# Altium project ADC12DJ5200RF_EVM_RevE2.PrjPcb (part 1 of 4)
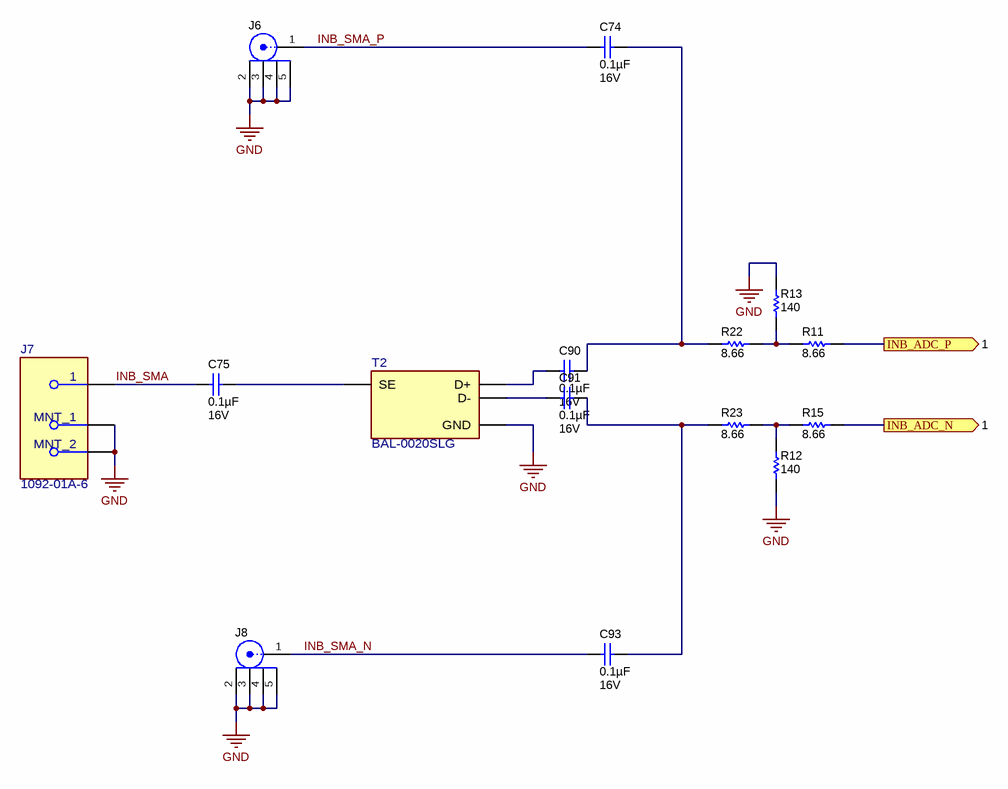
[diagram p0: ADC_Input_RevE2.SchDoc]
CopyrightYear: 2020; EVM_Orderable: N/A; PCB_Layout: DWG; PCB_Rev: E2; PRJ_Customer: Not For Public Release; PRJ_Engineer: DWG; PRJ_Number: N/A; PRJ_Title: ADC12DJ5200RF EVM; Rev: E2; TechSupport: http://www.ti.com/support; TID: N/A
15 sheets, 702 parts. Net scope: flat (ports and power ports of the same name join across sheets).
Board file: ADC12DJ5200RF_EVM_RevE2.PcbDoc
Sheets:
  ADC_Input_RevE2.SchDoc
  ADC_Power_RevE2.SchDoc
  ADC_RevE2.SchDoc
  Analog_Frontend_RevE2.SchDoc
  Clocks_RevE2.SchDoc
  Clocks2_RevE2.SchDoc
  Clocks3_RevE2.SchDoc
  FMC_RevE2.SchDoc
  GPIO_RevE2.SchDoc
  GPIO2_RevE2.SchDoc
  Misc_RevE2.SchDoc
  Power1_RevE2.SchDoc
  Power2_RevE2.SchDoc
  USB_RevE2.SchDoc
  Balun Test RevE2.SchDoc

## Sheet ADC_Input_RevE2.SchDoc: ADC EVM RF Input
size 431 x 279 mm; Date: Not shown in title block; ApprovedBy: Not shown in title block; CheckedBy: Not shown in title block; Author: Not shown in title block; CompanyName: Not shown in title block; DrawnBy: DWG; Engineer: Not shown in title block; Organization: Not shown in title block; Address1: Not shown in title block; Address2: Not shown in title block; Address3: Not shown in title block; Address4: Not shown in title block; DocumentNumber: 1; Revision: Use project parameter SCH_Rev; SheetNumber: 1; SheetTotal: 15; PageSetup: Record=PageOptions¦CenterHorizontal=True¦CenterVertical=True¦PrintScale=1.00¦XCorrection=1.00¦YCorrection=1.00¦PrintKind=0¦BorderSize=5000000¦LeftOffset=0¦BottomOffset=0¦Orientation=2¦PaperLength=1000¦PaperWidth=1000¦Scale=100¦PaperSource=15¦PrintQuality=600¦MediaType=1¦DitherType=10¦PaperKind=Letter¦PrintScaleMode=1

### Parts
C74  ValueDisplayed: 0.1µF  VDC_V: 16V  [0201_033]  (hidden comment: 0201BB104KW160)
C75  ValueDisplayed: 0.1µF  VDC_V: 16V  [0201_033]  (hidden comment: 0201BB104KW160)
C90  ValueDisplayed: 0.1µF  VDC_V: 16V  [0201_033]  (hidden comment: 0201BB104KW160)
C91  ValueDisplayed: 0.1µF  VDC_V: 16V  [0201_033]  (hidden comment: 0201BB104KW160)
C93  ValueDisplayed: 0.1µF  VDC_V: 16V  [0201_033]  (hidden comment: 0201BB104KW160)
J6  SASF546-P26-X1  [CONN_LTI_SASF546-P26-X1]  (value not drawn)
J7  1092-01A-6  [FP-1092-01A-6_RF_JACK_18MM94_12MM7-MFG]
J8  SASF546-P26-X1  [CONN_LTI_SASF546-P26-X1]  (value not drawn)
R11  ValueDisplayed: 8.66  [0201]  (hidden comment: RC0201FR-078R66L)
R12  ValueDisplayed: 140  [0201]  (hidden comment: RC0201FR-07140RL)
R13  ValueDisplayed: 140  [0201]  (hidden comment: RC0201FR-07140RL)
R15  ValueDisplayed: 8.66  [0201]  (hidden comment: RC0201FR-078R66L)
R22  ValueDisplayed: 8.66  [0201]  (hidden comment: RC0201FR-078R66L)
R23  ValueDisplayed: 8.66  [0201]  (hidden comment: RC0201FR-078R66L)
T2  BAL-0020SLG  [FP-BAL-0020SLG_SMT_BALUN_12MM70_5MM08-MFG]

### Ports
INB_ADC_N (out, see 1), INB_ADC_P (out, see 1)

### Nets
GND: J6.2 J6.3 J6.4 J6.5 J7.2(MNT_1) J7.3(MNT_2) J8.2 J8.3 J8.4 J8.5 R12.1 R13.2 T2.4(GND)
INB_ADC_N: R15.2 ; port INB_ADC_N
INB_ADC_P: R11.2 ; port INB_ADC_P
INB_SMA: C75.2 J7.1
INB_SMA_N: C93.2 J8.1
INB_SMA_P: C74.2 J6.1
NetC74_1: C74.1 C90.1 R22.1
NetC75_1: C75.1 T2.1(SE)
NetC90_2: C90.2 T2.3(D+)
NetC91_1: C91.1 C93.1 R23.1
NetC91_2: C91.2 T2.2(D-)
NetR11_1: R11.1 R13.1 R22.2
NetR12_2: R12.2 R15.1 R23.2

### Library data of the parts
C74 C75 C90 C91 C93 = CMP-0860981-1: CAP, CERM, 0.1 µF, 16 V,+/- 10%, X7R, 0201; Manufacturer: Passive Plus; Value: 0.1uF; Polarized: N; SizeY_mm: 0.3; TaMin_C: -55°C; U/M: EA; Cap_Case: 0201; AEC Category: Q200; SizeZ_mm: 0.33; SizeArea_mm2: 0.18; SizeX_mm: 0.6; Cap_F: 100nF; SizeAreaWB_mm2: 2.08; TaMax_C: 125°C
J6 J8 = CMP-0055826-1: Connector, SMA,Vertical, Thru hole w/SMT center pin; Manufacturer: Lighthorse Technologies; CT: TRUE; Green_REACh: Incomplete; CNHeader: FALSE; Green_Lifecycle: Not Set
J7 = CMP-0088081-2: End Launch 2.92mm (K) 40 GHz Jack (Female) Standard Block; Manufacturer: Southwest Microwave; ContactFinish: Gold; Shrouded: true
R11 R15 R22 R23 = CMP-0750119-1: RES, 8.66, 1%, 0.05 W, 0201; Manufacturer: Yageo; Value2: 0.05W; VDC_V: 50V; SizeZ_mm: 0.26; Value_Code: 8R66; AEC Category: Q200; TempCo: 350 ppm/C; SizeAreaWB_mm2: 2.08; Power_W: 50mW; AEC Qualified: N; EIA_Code: E96; SizeArea_mm2: 0.18; SizeX_mm: 0.6; SizeY_mm: 0.3; Value: 8.66
R12 R13 = CMP-0027355-2: RES, 140, 1%, 0.05 W, 0201; Manufacturer: Yageo America; Power_W: 50mW; TempCo: 200 ppm/C; Value_Code: 140R; U/M: EA; Value: 140; EIA_Code: E96; SizeX_mm: 0.6; SizeY_mm: 0.3; SizeZ_mm: 0.26; Value2: 0.05W; SizeArea_mm2: 0.18; AEC Qualified: N; VDC_V: 25V; AEC Category: Q200
T2 = CMP-0090705-1: 10 MHz to 20 GHz 1:2 Balun, Surface Mount; Manufacturer: Marki Microwave; Bandwidth: 19.99GHz; Filter Type: Band Pass; Frequency_Fixed: 0.01-20GHz; AEC Qualified: No; Insertion Loss: 7dB; SizeZ_mm: 2.79mm

## Sheet ADC_Power_RevE2.SchDoc: ADC EVM Power
size 431 x 279 mm; Date: Not shown in title block; ApprovedBy: Not shown in title block; CheckedBy: Not shown in title block; Author: Not shown in title block; CompanyName: Not shown in title block; DrawnBy: DWG; Engineer: Not shown in title block; Organization: Not shown in title block; Address1: Not shown in title block; Address2: Not shown in title block; Address3: Not shown in title block; Address4: Not shown in title block; DocumentNumber: 2; Revision: Use project parameter SCH_Rev; SheetNumber: 2; SheetTotal: 15; PageSetup: Record=PageOptions¦CenterHorizontal=True¦CenterVertical=True¦PrintScale=1.00¦XCorrection=1.00¦YCorrection=1.00¦PrintKind=0¦BorderSize=5000000¦LeftOffset=0¦BottomOffset=0¦Orientation=2¦PaperLength=1000¦PaperWidth=1000¦Scale=100¦PaperSource=15¦PrintQuality=600¦MediaType=1¦DitherType=10¦PaperKind=Letter¦PrintScaleMode=1
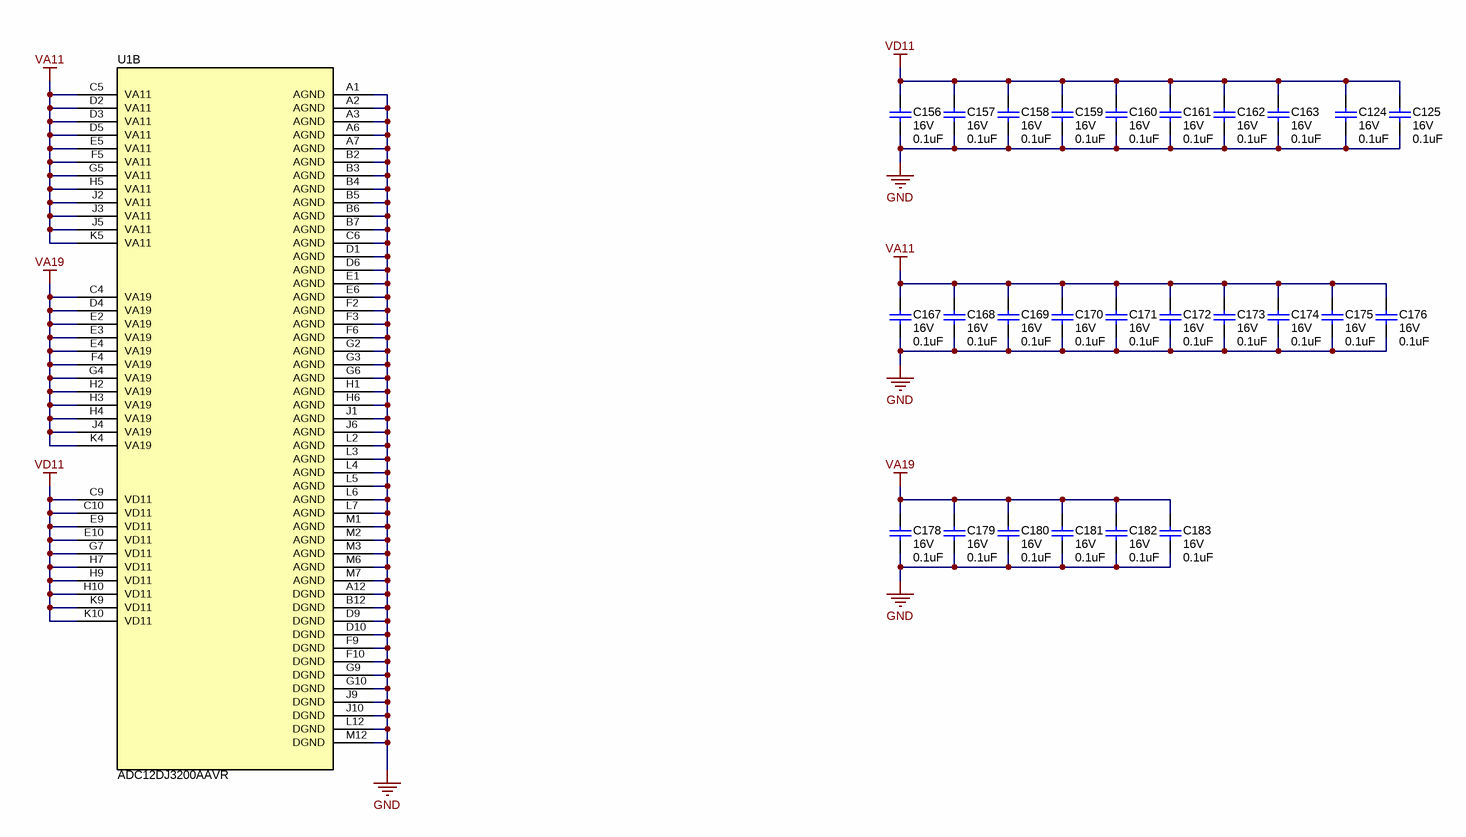
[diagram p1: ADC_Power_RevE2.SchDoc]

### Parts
C124  VDC_V: 16V  ValueDisplayed: 0.1uF  [0201L]  (hidden comment: GRM033Z71C104KE14D)
C125  VDC_V: 16V  ValueDisplayed: 0.1uF  [0201L]  (hidden comment: GRM033Z71C104KE14D)
C156  VDC_V: 16V  ValueDisplayed: 0.1uF  [0201L]  (hidden comment: GRM033Z71C104KE14D)
C157  VDC_V: 16V  ValueDisplayed: 0.1uF  [0201L]  (hidden comment: GRM033Z71C104KE14D)
C158  VDC_V: 16V  ValueDisplayed: 0.1uF  [0201L]  (hidden comment: GRM033Z71C104KE14D)
C159  VDC_V: 16V  ValueDisplayed: 0.1uF  [0201L]  (hidden comment: GRM033Z71C104KE14D)
C160  VDC_V: 16V  ValueDisplayed: 0.1uF  [0201L]  (hidden comment: GRM033Z71C104KE14D)
C161  VDC_V: 16V  ValueDisplayed: 0.1uF  [0201L]  (hidden comment: GRM033Z71C104KE14D)
C162  VDC_V: 16V  ValueDisplayed: 0.1uF  [0201L]  (hidden comment: GRM033Z71C104KE14D)
C163  VDC_V: 16V  ValueDisplayed: 0.1uF  [0201L]  (hidden comment: GRM033Z71C104KE14D)
C167  VDC_V: 16V  ValueDisplayed: 0.1uF  [0201L]  (hidden comment: GRM033Z71C104KE14D)
C168  VDC_V: 16V  ValueDisplayed: 0.1uF  [0201L]  (hidden comment: GRM033Z71C104KE14D)
C169  VDC_V: 16V  ValueDisplayed: 0.1uF  [0201L]  (hidden comment: GRM033Z71C104KE14D)
C170  VDC_V: 16V  ValueDisplayed: 0.1uF  [0201L]  (hidden comment: GRM033Z71C104KE14D)
C171  VDC_V: 16V  ValueDisplayed: 0.1uF  [0201L]  (hidden comment: GRM033Z71C104KE14D)
C172  VDC_V: 16V  ValueDisplayed: 0.1uF  [0201L]  (hidden comment: GRM033Z71C104KE14D)
C173  VDC_V: 16V  ValueDisplayed: 0.1uF  [0201L]  (hidden comment: GRM033Z71C104KE14D)
C174  VDC_V: 16V  ValueDisplayed: 0.1uF  [0201L]  (hidden comment: GRM033Z71C104KE14D)
C175  VDC_V: 16V  ValueDisplayed: 0.1uF  [0201L]  (hidden comment: GRM033Z71C104KE14D)
C176  VDC_V: 16V  ValueDisplayed: 0.1uF  [0201L]  (hidden comment: GRM033Z71C104KE14D)
C178  VDC_V: 16V  ValueDisplayed: 0.1uF  [0201L]  (hidden comment: GRM033Z71C104KE14D)
C179  VDC_V: 16V  ValueDisplayed: 0.1uF  [0201L]  (hidden comment: GRM033Z71C104KE14D)
C180  VDC_V: 16V  ValueDisplayed: 0.1uF  [0201L]  (hidden comment: GRM033Z71C104KE14D)
C181  VDC_V: 16V  ValueDisplayed: 0.1uF  [0201L]  (hidden comment: GRM033Z71C104KE14D)
C182  VDC_V: 16V  ValueDisplayed: 0.1uF  [0201L]  (hidden comment: GRM033Z71C104KE14D)
C183  VDC_V: 16V  ValueDisplayed: 0.1uF  [0201L]  (hidden comment: GRM033Z71C104KE14D)
U1  ADC12DJ3200AAVR  [AAV0144A]  (part B of 2)

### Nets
GND: C124.1 C125.1 C156.1 C157.1 C158.1 C159.1 C160.1 C161.1 C162.1 C163.1 C167.1 C168.1 C169.1 C170.1 C171.1 C172.1 C173.1 C174.1 C175.1 C176.1 C178.1 C179.1 C180.1 C181.1 C182.1 C183.1 U1.A1(AGND) U1.A2(AGND) U1.A3(AGND) U1.A6(AGND) U1.A7(AGND) U1.A12(DGND) U1.B2(AGND) U1.B3(AGND) U1.B4(AGND) U1.B5(AGND) U1.B6(AGND) U1.B7(AGND) U1.B12(DGND) U1.C6(AGND) U1.D1(AGND) U1.D6(AGND) U1.D9(DGND) U1.D10(DGND) U1.E1(AGND) U1.E6(AGND) U1.F2(AGND) U1.F3(AGND) U1.F6(AGND) U1.F9(DGND) U1.F10(DGND) U1.G2(AGND) U1.G3(AGND) U1.G6(AGND) U1.G9(DGND) U1.G10(DGND) U1.H1(AGND) U1.H6(AGND) U1.J1(AGND) U1.J6(AGND) U1.J9(DGND) U1.J10(DGND) U1.L2(AGND) U1.L3(AGND) U1.L4(AGND) U1.L5(AGND) U1.L6(AGND) U1.L7(AGND) U1.L12(DGND) U1.M1(AGND) U1.M2(AGND) U1.M3(AGND) U1.M6(AGND) U1.M7(AGND) U1.M12(DGND)
VA11: C167.2 C168.2 C169.2 C170.2 C171.2 C172.2 C173.2 C174.2 C175.2 C176.2 U1.C5(VA11) U1.D2(VA11) U1.D3(VA11) U1.D5(VA11) U1.E5(VA11) U1.F5(VA11) U1.G5(VA11) U1.H5(VA11) U1.J2(VA11) U1.J3(VA11) U1.J5(VA11) U1.K5(VA11)
VA19: C178.2 C179.2 C180.2 C181.2 C182.2 C183.2 U1.C4(VA19) U1.D4(VA19) U1.E2(VA19) U1.E3(VA19) U1.E4(VA19) U1.F4(VA19) U1.G4(VA19) U1.H2(VA19) U1.H3(VA19) U1.H4(VA19) U1.J4(VA19) U1.K4(VA19)
VD11: C124.2 C125.2 C156.2 C157.2 C158.2 C159.2 C160.2 C161.2 C162.2 C163.2 U1.C9(VD11) U1.C10(VD11) U1.E9(VD11) U1.E10(VD11) U1.G7(VD11) U1.H7(VD11) U1.H9(VD11) U1.H10(VD11) U1.K9(VD11) U1.K10(VD11)

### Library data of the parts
C124 C125 C156 C167 = CMP-0064970-1: CAP, CERM, 0.1 uF, 16 V,+/- 10%, X7R, 0201; Manufacturer: MuRata; TaMin_C: -55°C; Polarized: N; SizeAreaWB_mm2: 2.08; Value1: Unknown; U/M: EA; Value: 0.1uF; TaMax_C: 125°C; SizeZ_mm: 0.26; SizeX_mm: 0.6; SizeY_mm: 0.3; Cap_Case: 0201; SizeArea_mm2: 0.18; CompType: Capacitor; Cap_F: 100nF; AEC Category: Q200
C157-C163 C168-C176 C178-C183 = CMP-0064970-1: CAP, CERM, 0.1 uF, 16 V,+/- 10%, X7R, 0201; Manufacturer: MuRata; TaMin_C: -55°C; Polarized: N; SizeAreaWB_mm2: 2.08; Value1: Unknown; U/M: EA; Value: 0.1uF; TaMax_C: 125°C; SizeZ_mm: 0.26; SizeX_mm: 0.6; SizeY_mm: 0.3; Cap_Case: 0201; SizeArea_mm2: 0.18; Cap_F: 100nF; AEC Category: Q200
U1 = CMP-0065050-3: 6.4-GSPS Single Channel or 3.2-GSPS Dual Channel 12-bit Analog-to-Digital Converter (ADC) Family, AAV0144A (FCBGA-144); Alternate PartNumber: ADC12DJ3200AAVT; Manufacturer: Texas Instruments; SizeZ_mm: 1.94; SizeX_mm: 10.0; SizeArea_mm2: 100.0; CompType: IC; U/M: EA; SizeAreaWB_mm2: 144.0

## Sheet ADC_RevE2.SchDoc: ADC EVM IO
size 431 x 279 mm; Date: Not shown in title block; ApprovedBy: Not shown in title block; CheckedBy: Not shown in title block; Author: Not shown in title block; CompanyName: Not shown in title block; DrawnBy: DWG; Engineer: DWG; Organization: Not shown in title block; Address1: Not shown in title block; Address2: Not shown in title block; Address3: Not shown in title block; Address4: Not shown in title block; DocumentNumber: 3; Revision: Use project parameter SCH_Rev; SheetNumber: 3; SheetTotal: 15; PageSetup: Record=PageOptions¦CenterHorizontal=True¦CenterVertical=True¦PrintScale=1.00¦XCorrection=1.00¦YCorrection=1.00¦PrintKind=0¦BorderSize=5000000¦LeftOffset=0¦BottomOffset=0¦Orientation=2¦PaperLength=1000¦PaperWidth=1000¦Scale=100¦PaperSource=15¦PrintQuality=600¦MediaType=1¦DitherType=10¦PaperKind=Letter¦PrintScaleMode=1
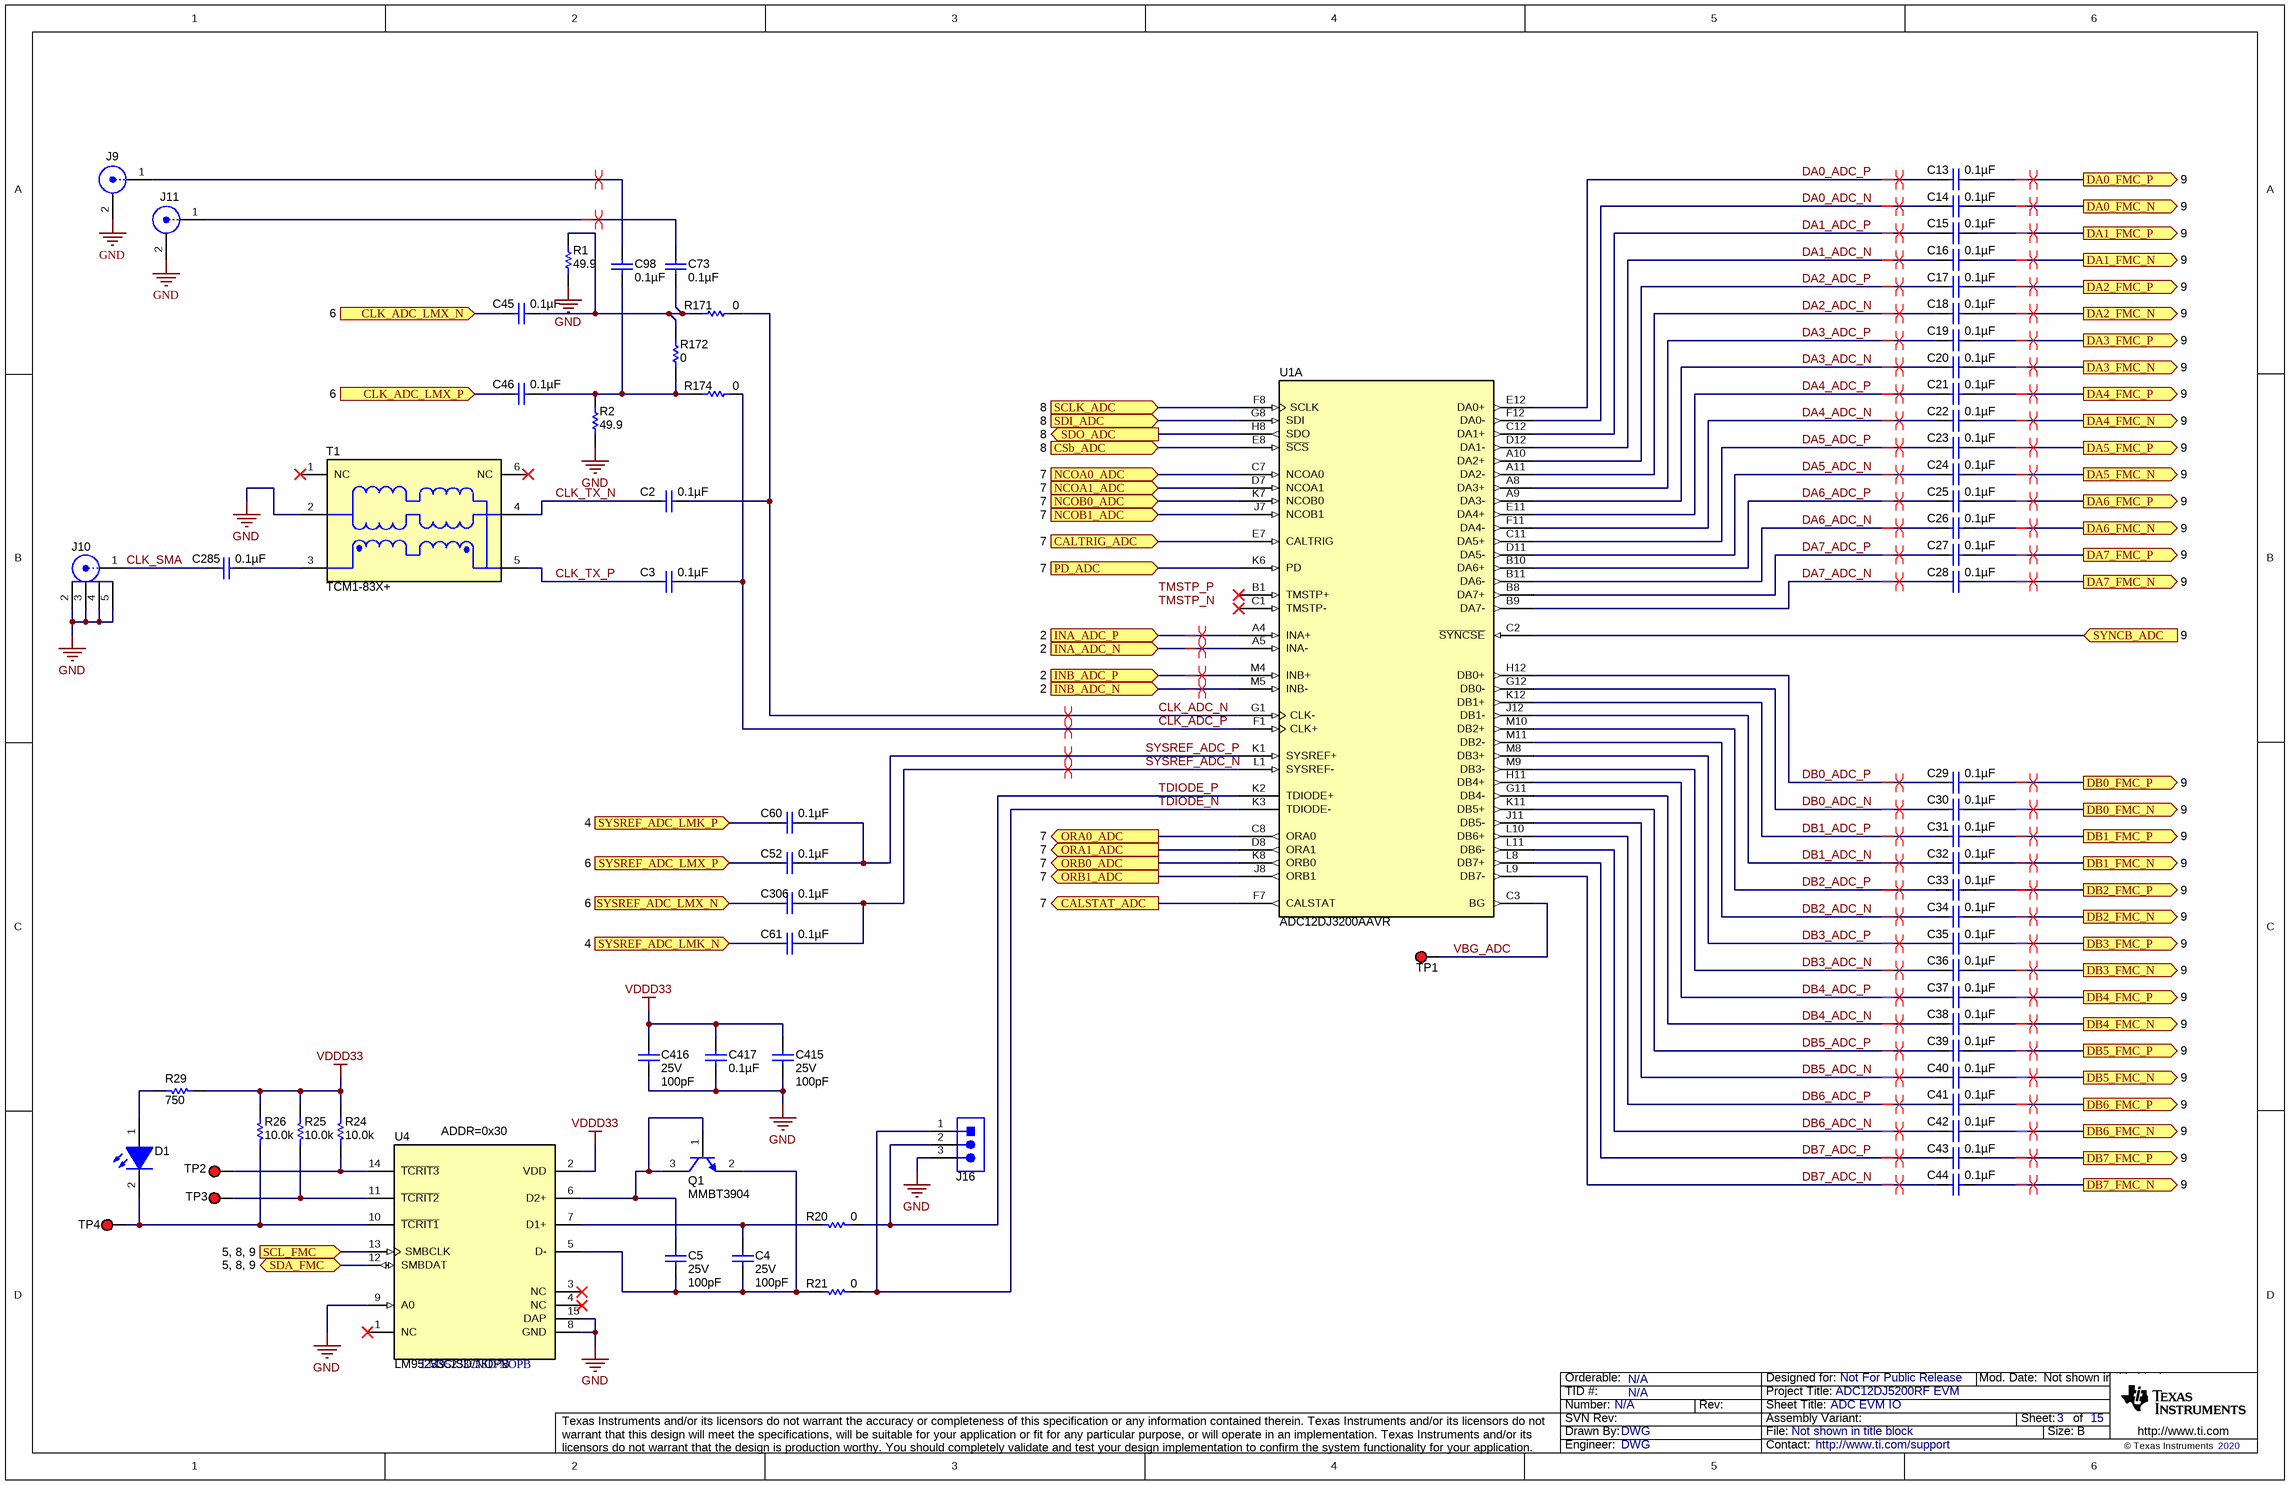
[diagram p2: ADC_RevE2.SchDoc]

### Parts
C2  ValueDisplayed: 0.1µF  [0201_033L]  (hidden comment: 0201BB104KW160)
C3  ValueDisplayed: 0.1µF  [0201_033L]  (hidden comment: 0201BB104KW160)
C4  VDC_V: 25V  ValueDisplayed: 100pF  [0201_033]  (hidden comment: C0603C0G1E101J030BA)
C5  VDC_V: 25V  ValueDisplayed: 100pF  [0201_033]  (hidden comment: C0603C0G1E101J030BA)
C13  ValueDisplayed: 0.1µF  [0201_033L]  (hidden comment: 0201BB104KW160)
C14  ValueDisplayed: 0.1µF  [0201_033L]  (hidden comment: 0201BB104KW160)
C15  ValueDisplayed: 0.1µF  [0201_033L]  (hidden comment: 0201BB104KW160)
C16  ValueDisplayed: 0.1µF  [0201_033L]  (hidden comment: 0201BB104KW160)
C17  ValueDisplayed: 0.1µF  [0201_033L]  (hidden comment: 0201BB104KW160)
C18  ValueDisplayed: 0.1µF  [0201_033L]  (hidden comment: 0201BB104KW160)
C19  ValueDisplayed: 0.1µF  [0201_033L]  (hidden comment: 0201BB104KW160)
C20  ValueDisplayed: 0.1µF  [0201_033L]  (hidden comment: 0201BB104KW160)
C21  ValueDisplayed: 0.1µF  [0201_033L]  (hidden comment: 0201BB104KW160)
C22  ValueDisplayed: 0.1µF  [0201_033L]  (hidden comment: 0201BB104KW160)
C23  ValueDisplayed: 0.1µF  [0201_033L]  (hidden comment: 0201BB104KW160)
C24  ValueDisplayed: 0.1µF  [0201_033L]  (hidden comment: 0201BB104KW160)
C25  ValueDisplayed: 0.1µF  [0201_033L]  (hidden comment: 0201BB104KW160)
C26  ValueDisplayed: 0.1µF  [0201_033L]  (hidden comment: 0201BB104KW160)
C27  ValueDisplayed: 0.1µF  [0201_033L]  (hidden comment: 0201BB104KW160)
C28  ValueDisplayed: 0.1µF  [0201_033L]  (hidden comment: 0201BB104KW160)
C29  ValueDisplayed: 0.1µF  [0201_033L]  (hidden comment: 0201BB104KW160)
C30  ValueDisplayed: 0.1µF  [0201_033L]  (hidden comment: 0201BB104KW160)
C31  ValueDisplayed: 0.1µF  [0201_033L]  (hidden comment: 0201BB104KW160)
C32  ValueDisplayed: 0.1µF  [0201_033L]  (hidden comment: 0201BB104KW160)
C33  ValueDisplayed: 0.1µF  [0201_033L]  (hidden comment: 0201BB104KW160)
C34  ValueDisplayed: 0.1µF  [0201_033L]  (hidden comment: 0201BB104KW160)
C35  ValueDisplayed: 0.1µF  [0201_033L]  (hidden comment: 0201BB104KW160)
C36  ValueDisplayed: 0.1µF  [0201_033L]  (hidden comment: 0201BB104KW160)
C37  ValueDisplayed: 0.1µF  [0201_033L]  (hidden comment: 0201BB104KW160)
C38  ValueDisplayed: 0.1µF  [0201_033L]  (hidden comment: 0201BB104KW160)
C39  ValueDisplayed: 0.1µF  [0201_033L]  (hidden comment: 0201BB104KW160)
C40  ValueDisplayed: 0.1µF  [0201_033L]  (hidden comment: 0201BB104KW160)
C41  ValueDisplayed: 0.1µF  [0201_033L]  (hidden comment: 0201BB104KW160)
C42  ValueDisplayed: 0.1µF  [0201_033L]  (hidden comment: 0201BB104KW160)
C43  ValueDisplayed: 0.1µF  [0201_033L]  (hidden comment: 0201BB104KW160)
C44  ValueDisplayed: 0.1µF  [0201_033L]  (hidden comment: 0201BB104KW160)
C45  ValueDisplayed: 0.1µF  [0201_033L]  (hidden comment: 0201BB104KW160)
C46  ValueDisplayed: 0.1µF  [0201_033L]  (hidden comment: 0201BB104KW160)
C52  ValueDisplayed: 0.1µF  [0201_033L]  (hidden comment: 0201BB104KW160)
C60  ValueDisplayed: 0.1µF  [0201_033L]  (hidden comment: 0201BB104KW160)
C61  ValueDisplayed: 0.1µF  [0201_033L]  (hidden comment: 0201BB104KW160)
C73  ValueDisplayed: 0.1µF  [0201_033L]  (hidden comment: 0201BB104KW160)
C98  ValueDisplayed: 0.1µF  [0201_033L]  (hidden comment: 0201BB104KW160)
C285  ValueDisplayed: 0.1µF  [0201_033L]  (hidden comment: 0201BB104KW160)
C306  ValueDisplayed: 0.1µF  [0201_033L]  (hidden comment: 0201BB104KW160)
C415  VDC_V: 25V  ValueDisplayed: 100pF  [0201_033]  (hidden comment: C0603C0G1E101J030BA)
C416  VDC_V: 25V  ValueDisplayed: 100pF  [0201_033]  (hidden comment: C0603C0G1E101J030BA)
C417  ValueDisplayed: 0.1µF  [0201_033L]  (hidden comment: 0201BB104KW160)
D1  LTST-C190KRKT  [LED_LTST-C190_Red]  (value not drawn)
J9  0853050232  [Molex_0853050232]  (value not drawn)
J10  SASF546-P26-X1  [CONN_LTI_SASF546-P26-X1]  (value not drawn)
J11  0853050232  [Molex_0853050232]  (value not drawn)
J16  61300311121  [WURTH_61300311121]  (value not drawn)
Q1  MMBT3904  [SOT-23]
R1  ValueDisplayed: 49.9  [0201L]  (hidden comment: ERJ-1GEF49R9C)
R2  ValueDisplayed: 49.9  [0201L]  (hidden comment: ERJ-1GEF49R9C)
R20  ValueDisplayed: 0  [0201]  (hidden comment: CRCW02010000Z0ED)
R21  ValueDisplayed: 0  [0201]  (hidden comment: CRCW02010000Z0ED)
R24  ValueDisplayed: 10.0k  [0201]  (hidden comment: RC0201FR-7D10KL)
R25  ValueDisplayed: 10.0k  [0201]  (hidden comment: RC0201FR-7D10KL)
R26  ValueDisplayed: 10.0k  [0201]  (hidden comment: RC0201FR-7D10KL)
R29  ValueDisplayed: 750  [0201]  (hidden comment: RC0201FR-07750RL)
R171  ValueDisplayed: 0  [0201L]  (hidden comment: CRCW02010000Z0ED)
R172  ValueDisplayed: 0  [0201L]  (hidden comment: CRCW02010000Z0ED)
R174  ValueDisplayed: 0  [0201L]  (hidden comment: CRCW02010000Z0ED)
T1  TCM1-83X+  [MNC_TCM1-83X+]
TP1  5000  [Keystone5000]  (value not drawn)
TP2  5000  [Keystone5000]  (value not drawn)
TP3  5000  [Keystone5000]  (value not drawn)
TP4  5000  [Keystone5000]  (value not drawn)
U1  ADC12DJ3200AAVR  [AAV0144A]  (part A of 2)
U4  LM95233CISD/NOPB  [NHL0014B]

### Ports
CALSTAT_ADC (out, see 7), CALTRIG_ADC (in, see 7), CLK_ADC_LMX_N (in, see 6), CLK_ADC_LMX_P (in, see 6), CSb_ADC (in, see 8), DA0_FMC_N (out, see 9), DA0_FMC_P (out, see 9), DA1_FMC_N (out, see 9), DA1_FMC_P (out, see 9), DA2_FMC_N (out, see 9), DA2_FMC_P (out, see 9), DA3_FMC_N (out, see 9), DA3_FMC_P (out, see 9), DA4_FMC_N (out, see 9), DA4_FMC_P (out, see 9), DA5_FMC_N (out, see 9), DA5_FMC_P (out, see 9), DA6_FMC_N (out, see 9), DA6_FMC_P (out, see 9), DA7_FMC_N (out, see 9), DA7_FMC_P (out, see 9), DB0_FMC_N (out, see 9), DB0_FMC_P (out, see 9), DB1_FMC_N (out, see 9), DB1_FMC_P (out, see 9), DB2_FMC_N (out, see 9), DB2_FMC_P (out, see 9), DB3_FMC_N (out, see 9), DB3_FMC_P (out, see 9), DB4_FMC_N (out, see 9), DB4_FMC_P (out, see 9), DB5_FMC_N (out, see 9), DB5_FMC_P (out, see 9), DB6_FMC_N (out, see 9), DB6_FMC_P (out, see 9), DB7_FMC_N (out, see 9), DB7_FMC_P (out, see 9), INA_ADC_N (in, see 2), INA_ADC_P (in, see 2), INB_ADC_N (in, see 2), INB_ADC_P (in, see 2), NCOA0_ADC (in, see 7), NCOA1_ADC (in, see 7), NCOB0_ADC (in, see 7), NCOB1_ADC (in, see 7), ORA0_ADC (out, see 7), ORA1_ADC (out, see 7), ORB0_ADC (out, see 7), ORB1_ADC (out, see 7), PD_ADC (in, see 7), SCL_FMC (in, see 5, 8, 9), SCLK_ADC (in, see 8), SDA_FMC (bidir, see 5, 8, 9), SDI_ADC (in, see 8), SDO_ADC (out, see 8), SYNCB_ADC (in, see 9), SYSREF_ADC_LMK_N (in, see 4), SYSREF_ADC_LMK_P (in, see 4), SYSREF_ADC_LMX_N (in, see 6), SYSREF_ADC_LMX_P (in, see 6)

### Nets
GND: C415.2 C416.2 C417.2 J9.2 J10.2 J10.3 J10.4 J10.5 J11.2 J16.3 R1.1 R2.1 T1.2 U4.8(GND) U4.9(A0) U4.15(DAP)
VDDD33: C415.1 C416.1 C417.1 R24.2 R25.2 R26.2 R29.1 U4.2(VDD)
CALSTAT_ADC: U1.F7(CALSTAT) ; port CALSTAT_ADC
CALTRIG_ADC: U1.E7(CALTRIG) ; port CALTRIG_ADC
CLK_ADC_LMX_N: C45.2 ; port CLK_ADC_LMX_N
CLK_ADC_LMX_P: C46.2 ; port CLK_ADC_LMX_P
CLK_ADC_N: C2.1 R171.2 U1.G1(CLK-)
CLK_ADC_P: C3.1 R174.2 U1.F1(CLK+)
CLK_SMA: C285.2 J10.1
CLK_TX_N: C2.2 T1.4
CLK_TX_P: C3.2 T1.5
CSb_ADC: U1.E8(~{SCS}) ; port CSb_ADC
DA0_ADC_N: C14.2 U1.F12(DA0-)
DA0_ADC_P: C13.2 U1.E12(DA0+)
DA0_FMC_N: C14.1 ; port DA0_FMC_N
DA0_FMC_P: C13.1 ; port DA0_FMC_P
DA1_ADC_N: C16.2 U1.D12(DA1-)
DA1_ADC_P: C15.2 U1.C12(DA1+)
DA1_FMC_N: C16.1 ; port DA1_FMC_N
DA1_FMC_P: C15.1 ; port DA1_FMC_P
DA2_ADC_N: C18.2 U1.A11(DA2-)
DA2_ADC_P: C17.2 U1.A10(DA2+)
DA2_FMC_N: C18.1 ; port DA2_FMC_N
DA2_FMC_P: C17.1 ; port DA2_FMC_P
DA3_ADC_N: C20.2 U1.A9(DA3-)
DA3_ADC_P: C19.2 U1.A8(DA3+)
DA3_FMC_N: C20.1 ; port DA3_FMC_N
DA3_FMC_P: C19.1 ; port DA3_FMC_P
DA4_ADC_N: C22.2 U1.F11(DA4-)
DA4_ADC_P: C21.2 U1.E11(DA4+)
DA4_FMC_N: C22.1 ; port DA4_FMC_N
DA4_FMC_P: C21.1 ; port DA4_FMC_P
DA5_ADC_N: C24.2 U1.D11(DA5-)
DA5_ADC_P: C23.2 U1.C11(DA5+)
DA5_FMC_N: C24.1 ; port DA5_FMC_N
DA5_FMC_P: C23.1 ; port DA5_FMC_P
DA6_ADC_N: C26.2 U1.B11(DA6-)
DA6_ADC_P: C25.2 U1.B10(DA6+)
DA6_FMC_N: C26.1 ; port DA6_FMC_N
DA6_FMC_P: C25.1 ; port DA6_FMC_P
DA7_ADC_N: C28.2 U1.B9(DA7-)
DA7_ADC_P: C27.2 U1.B8(DA7+)
DA7_FMC_N: C28.1 ; port DA7_FMC_N
DA7_FMC_P: C27.1 ; port DA7_FMC_P
DB0_ADC_N: C30.2 U1.G12(DB0-)
DB0_ADC_P: C29.2 U1.H12(DB0+)
DB0_FMC_N: C30.1 ; port DB0_FMC_N
DB0_FMC_P: C29.1 ; port DB0_FMC_P
DB1_ADC_N: C32.2 U1.J12(DB1-)
DB1_ADC_P: C31.2 U1.K12(DB1+)
DB1_FMC_N: C32.1 ; port DB1_FMC_N
DB1_FMC_P: C31.1 ; port DB1_FMC_P
DB2_ADC_N: C34.2 U1.M11(DB2-)
DB2_ADC_P: C33.2 U1.M10(DB2+)
DB2_FMC_N: C34.1 ; port DB2_FMC_N
DB2_FMC_P: C33.1 ; port DB2_FMC_P
DB3_ADC_N: C36.2 U1.M9(DB3-)
DB3_ADC_P: C35.2 U1.M8(DB3+)
DB3_FMC_N: C36.1 ; port DB3_FMC_N
DB3_FMC_P: C35.1 ; port DB3_FMC_P
DB4_ADC_N: C38.2 U1.G11(DB4-)
DB4_ADC_P: C37.2 U1.H11(DB4+)
DB4_FMC_N: C38.1 ; port DB4_FMC_N
DB4_FMC_P: C37.1 ; port DB4_FMC_P
DB5_ADC_N: C40.2 U1.J11(DB5-)
DB5_ADC_P: C39.2 U1.K11(DB5+)
DB5_FMC_N: C40.1 ; port DB5_FMC_N
DB5_FMC_P: C39.1 ; port DB5_FMC_P
DB6_ADC_N: C42.2 U1.L11(DB6-)
DB6_ADC_P: C41.2 U1.L10(DB6+)
DB6_FMC_N: C42.1 ; port DB6_FMC_N
DB6_FMC_P: C41.1 ; port DB6_FMC_P
DB7_ADC_N: C44.2 U1.L9(DB7-)
DB7_ADC_P: C43.2 U1.L8(DB7+)
DB7_FMC_N: C44.1 ; port DB7_FMC_N
DB7_FMC_P: C43.1 ; port DB7_FMC_P
INA_ADC_N: U1.A5(INA-) ; port INA_ADC_N
INA_ADC_P: U1.A4(INA+) ; port INA_ADC_P
INB_ADC_N: U1.M5(INB-) ; port INB_ADC_N
INB_ADC_P: U1.M4(INB+) ; port INB_ADC_P
NCOA0_ADC: U1.C7(NCOA0) ; port NCOA0_ADC
NCOA1_ADC: U1.D7(NCOA1) ; port NCOA1_ADC
NCOB0_ADC: U1.K7(NCOB0) ; port NCOB0_ADC
NCOB1_ADC: U1.J7(NCOB1) ; port NCOB1_ADC
ORA0_ADC: U1.C8(ORA0) ; port ORA0_ADC
ORA1_ADC: U1.D8(ORA1) ; port ORA1_ADC
ORB0_ADC: U1.K8(ORB0) ; port ORB0_ADC
ORB1_ADC: U1.J8(ORB1) ; port ORB1_ADC
PD_ADC: U1.K6(PD) ; port PD_ADC
SCL_FMC: U4.13(SMBCLK) ; port SCL_FMC
SCLK_ADC: U1.F8(SCLK) ; port SCLK_ADC
SDA_FMC: U4.12(SMBDAT) ; port SDA_FMC
SDI_ADC: U1.G8(SDI) ; port SDI_ADC
SDO_ADC: U1.H8(SDO) ; port SDO_ADC
SYNCB_ADC: U1.C2(~{SYNCSE}) ; port SYNCB_ADC
SYSREF_ADC_LMK_N: C61.2 ; port SYSREF_ADC_LMK_N
SYSREF_ADC_LMK_P: C60.2 ; port SYSREF_ADC_LMK_P
SYSREF_ADC_LMX_N: C306.2 ; port SYSREF_ADC_LMX_N
SYSREF_ADC_LMX_P: C52.2 ; port SYSREF_ADC_LMX_P
SYSREF_ADC_N: C61.1 C306.1 U1.L1(SYSREF-)
SYSREF_ADC_P: C52.1 C60.1 U1.K1(SYSREF+)
TDIODE_N: J16.1 R21.1 U1.K3(TDIODE-)
TDIODE_P: J16.2 R20.1 U1.K2(TDIODE+)
VBG_ADC: TP1.1 U1.C3(BG)
NetC4_1: C4.1 R20.2 U4.7(D1+)
NetC4_2: C4.2 C5.2 Q1.2(E) R21.2 U4.5(D-)
NetC5_1: C5.1 Q1.1(B) Q1.3(C) U4.6(D2+)
NetC45_1: C45.1 C73.2 R1.2 R171.1 R172.2
NetC46_1: C46.1 C98.2 R2.2 R172.1 R174.1
NetC73_1: C73.1 J11.1
NetC98_1: C98.1 J9.1
NetC285_1: C285.1 T1.3
NetD1_1: D1.1(A) R29.2
NetD1_2: D1.2(K) R26.1 TP4.1 U4.10(~{TCRIT1})
NetR24_1: R24.1 TP2.1 U4.14(~{TCRIT3})
NetR25_1: R25.1 TP3.1 U4.11(~{TCRIT2})

Not connected (* = marked no-connect by the designer): T1 1(NC)* 6(NC)*; U1 B1(TMSTP+)* C1(TMSTP-)*; U4 1(NC)* 3(NC)* 4(NC)*

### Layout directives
differential pair: CLK_ADC_N, CLK_ADC_P, DA0_ADC_N, DA0_ADC_P, DA0_FMC_N, DA0_FMC_P, DA1_ADC_N, DA1_ADC_P, DA1_FMC_N, DA1_FMC_P, DA2_ADC_N, DA2_ADC_P, DA2_FMC_N, DA2_FMC_P, DA3_ADC_N, DA3_ADC_P, DA3_FMC_N, DA3_FMC_P, DA4_ADC_N, DA4_ADC_P, DA4_FMC_N, DA4_FMC_P, DA5_ADC_N, DA5_ADC_P, DA5_FMC_N, DA5_FMC_P, DA6_ADC_N, DA6_ADC_P, DA6_FMC_N, DA6_FMC_P, DA7_ADC_N, DA7_ADC_P, DA7_FMC_N, DA7_FMC_P, DB0_ADC_N, DB0_ADC_P, DB0_FMC_N, DB0_FMC_P, DB1_ADC_N, DB1_ADC_P, DB1_FMC_N, DB1_FMC_P, DB2_ADC_N, DB2_ADC_P, DB2_FMC_N, DB2_FMC_P, DB3_ADC_N, DB3_ADC_P, DB3_FMC_N, DB3_FMC_P, DB4_ADC_N, DB4_ADC_P, DB4_FMC_N, DB4_FMC_P, DB5_ADC_N, DB5_ADC_P, DB5_FMC_N, DB5_FMC_P, DB6_ADC_N, DB6_ADC_P, DB6_FMC_N, DB6_FMC_P, DB7_ADC_N, DB7_ADC_P, DB7_FMC_N, DB7_FMC_P, INA_ADC_N, INA_ADC_P, INB_ADC_N, INB_ADC_P, NetC73_1, NetC98_1, SYSREF_ADC_N, SYSREF_ADC_P

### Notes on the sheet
- (near U4) ADDR=0x30
- Labels drawn without touching a wire or pin: TMSTP_N, TMSTP_P

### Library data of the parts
C2 C3 C13-C46 C52 C60 C61 C73 C98 C285 C306 C417 = CMP-0860981-1: CAP, CERM, 0.1 µF, 16 V,+/- 10%, X7R, 0201; Manufacturer: Passive Plus; Cap_F: 100nF; SizeAreaWB_mm2: 2.08; SizeArea_mm2: 0.18; AEC Qualified: N; AEC Category: Q200; Value: 0.1uF; TaMax_C: 125°C; SizeZ_mm: 0.33; TaMin_C: -55°C; VDC_V: 16V; SizeY_mm: 0.3; U/M: EA; SizeX_mm: 0.6; Cap_Case: 0201
C4 C5 C415 C416 = CMP-0009632-3: CAP, CERM, 100 pF, 25 V, +/- 5%, C0G/NP0, 0201; Manufacturer: TDK; TaMin_C: -55°C; Polarized: N; SizeAreaWB_mm2: 2.08; Value1: Unknown; U/M: EA; Value: 100pF; TaMax_C: 125°C; SizeZ_mm: 0.33; SizeX_mm: 0.6; SizeY_mm: 0.3; Cap_Case: 0201; SizeArea_mm2: 0.18; AEC Category: Q200
D1 = CMP-0078131-2: LED, Red, SMD; Manufacturer: Lite-On; Vr_V: 5V; Power_TotalModule: 62.5mW; Angle: 130; Ir_A: 10µA; Green_REACh: Incomplete; Io_A: 20mA; Vf_V: 2V; Green_Lifecycle: Not Set; Value1: .0625W; Type: AlInGaP
J9 J11 = CMP-0077224-1: Plug, 50 Ohm, Straight, SMT; Manufacturer: Molex; Cert_UL: Y; ContactFinish: Gold; CT: False; Gender: Male; Voltage_V: 335V
J10 = CMP-0055826-1: as J6 on sheet ADC_Input_RevE2
J16 = CMP-0054796-2: Header, 2.54 mm, 3x1, Gold, TH; Manufacturer: Wurth Elektronik; Green_Lifecycle: Active; Green_REACh: Passed; Cert_UL: Y; Gender: Male; Pitch_mm: 2.54; Row_Count: 1; Shrouded: N
Q1 = CMP-0000386-2: Transistor, NPN, 40 V, 0.2 A, SOT-23; Manufacturer: Fairchild Semiconductor; TaMax_C: 150°C; Value2: 300; Value1: 0.2 A; Vcesat1_V: 2dV; SizeX_mm: 2.5; SizeY_mm: 3; TaMin_C: -55°C; IcRated_A: 2dA; CompType: BJT; SizeZ_mm: 1.1; Value: 40 V; SizeArea_mm2: 7.5; NPN: 1; Vceo_V: 40V; PNP: 0; AEC Category: Q101; SizeAreaWB_mm2: 14; U/M: EA
R1 R2 = CMP-0027289-3: RES, 49.9, 1%, 0.05 W, AEC-Q200 Grade 1, 0201; Manufacturer: Panasonic; Power_W: 50mW; TempCo: 200 ppm/C; Value_Code: 49R9; Value: 49.9; EIA_Code: E96; SizeX_mm: 0.6; SizeY_mm: 0.3; SizeZ_mm: 0.26; Value2: 0.05W; SizeArea_mm2: 0.18; AEC Qualified: Y; VDC_V: 25V; AEC Category: Q200; AEC Grade: 1; SizeAreaWB_mm2: 2.08
R20 R21 = CMP-0027008-4: RES, 0, 5%, 0.05 W, 0201; Manufacturer: Vishay-Dale; Power_W: 50mW; TempCo: ppm/C; Value_Code: 0000; Value: 0; EIA_Code: E24; SizeX_mm: 0.6; SizeY_mm: 0.3; SizeZ_mm: 0.26; Value2: 0.05W; SizeArea_mm2: 0.18; AEC Qualified: N; AEC Category: Q200
R24-R26 = CMP-0027945-1: RES, 10.0 k, 1%, 0.05 W, 0201; Manufacturer: Yageo America; Power_W: 50mW; TempCo: 200 ppm/C; Value_Code: 10k0; U/M: EA; Value: 10.0k; EIA_Code: E96; Res_ohm: 10k; SizeX_mm: 0.6; SizeY_mm: 0.3; SizeZ_mm: 0.26; Value2: 0.05W; SizeArea_mm2: 0.18; AEC Qualified: N; VDC_V: 25V; AEC Category: Q200
R29 = CMP-0027865-1: RES, 750, 1%, 0.05 W, 0201; Manufacturer: Yageo America; Power_W: 50mW; TempCo: 200 ppm/C; Value_Code: 750R; U/M: EA; Value: 750; EIA_Code: E96; SizeX_mm: 0.6; SizeY_mm: 0.3; SizeZ_mm: 0.26; Value2: 0.05W; SizeArea_mm2: 0.18; AEC Qualified: N; VDC_V: 25V; AEC Category: Q200
R171 R172 R174 = CMP-0027008-4: RES, 0, 5%, 0.05 W, 0201; Manufacturer: Vishay-Dale; Power_W: 50mW; TempCo: ppm/C; Value_Code: 0000; Value: 0; EIA_Code: E24; SizeX_mm: 0.6; SizeY_mm: 0.3; SizeZ_mm: 0.26; Value2: 0.05W; SizeArea_mm2: 0.18; CompType: Resistor; AEC Qualified: N; AEC Category: Q200
T1 = CMP-0030469-2: RF Transformer, 50 Ohm, SMT; Manufacturer: Minicircuits; SizeZ_mm: 4.3942; SizeX_mm: 3.81; SizeY_mm: 4.06; SizeArea_mm2: 15.4686; SizeAreaWB_mm2: 24.3386
TP1-TP4 = CMP-0055137-1: Test Point, Miniature, Red, TH; Manufacturer: Keystone; CNHeader: FALSE; Green_Lifecycle: Active; Green_REACh: Passed; ContactFinish: Silver; CT: TRUE
U1 = CMP-0065050-3: as U1 on sheet ADC_Power_RevE2
U4 = CMP-0073387-3: +/-2degC Dual Remote and Local Temperature Sensor with TruTherm Technology and SMBus Interface, NHL0014B (WSON-14); Manufacturer: Texas Instruments; CompType: IC; AEC Category: Q200; AEC Qualified: N; Rating: Catalog; SizeArea_mm2: 16.0; SizeAreaWB_mm2: 25.0; SizeX_mm: 4.0; SizeZ_mm: 0.8

## Sheet Analog_Frontend_RevE2.SchDoc
size 431 x 279 mm; Date: Not shown in title block; ApprovedBy: Not shown in title block; CheckedBy: Not shown in title block; Author: Not shown in title block; CompanyName: Not shown in title block; Engineer: Not shown in title block; Organization: Not shown in title block; Address1: Not shown in title block; Address2: Not shown in title block; Address3: Not shown in title block; Address4: Not shown in title block; DocumentNumber: 4; Revision: Use project parameter SCH_Rev; SheetNumber: 4; SheetTotal: 15; PageSetup: Record=PageOptions¦CenterHorizontal=True¦CenterVertical=True¦PrintScale=1.00¦XCorrection=1.00¦YCorrection=1.00¦PrintKind=0¦BorderSize=5000000¦LeftOffset=0¦BottomOffset=0¦Orientation=2¦PaperLength=1000¦PaperWidth=1000¦Scale=100¦PaperSource=15¦PrintQuality=600¦MediaType=1¦DitherType=10¦PaperKind=Letter¦PrintScaleMode=1
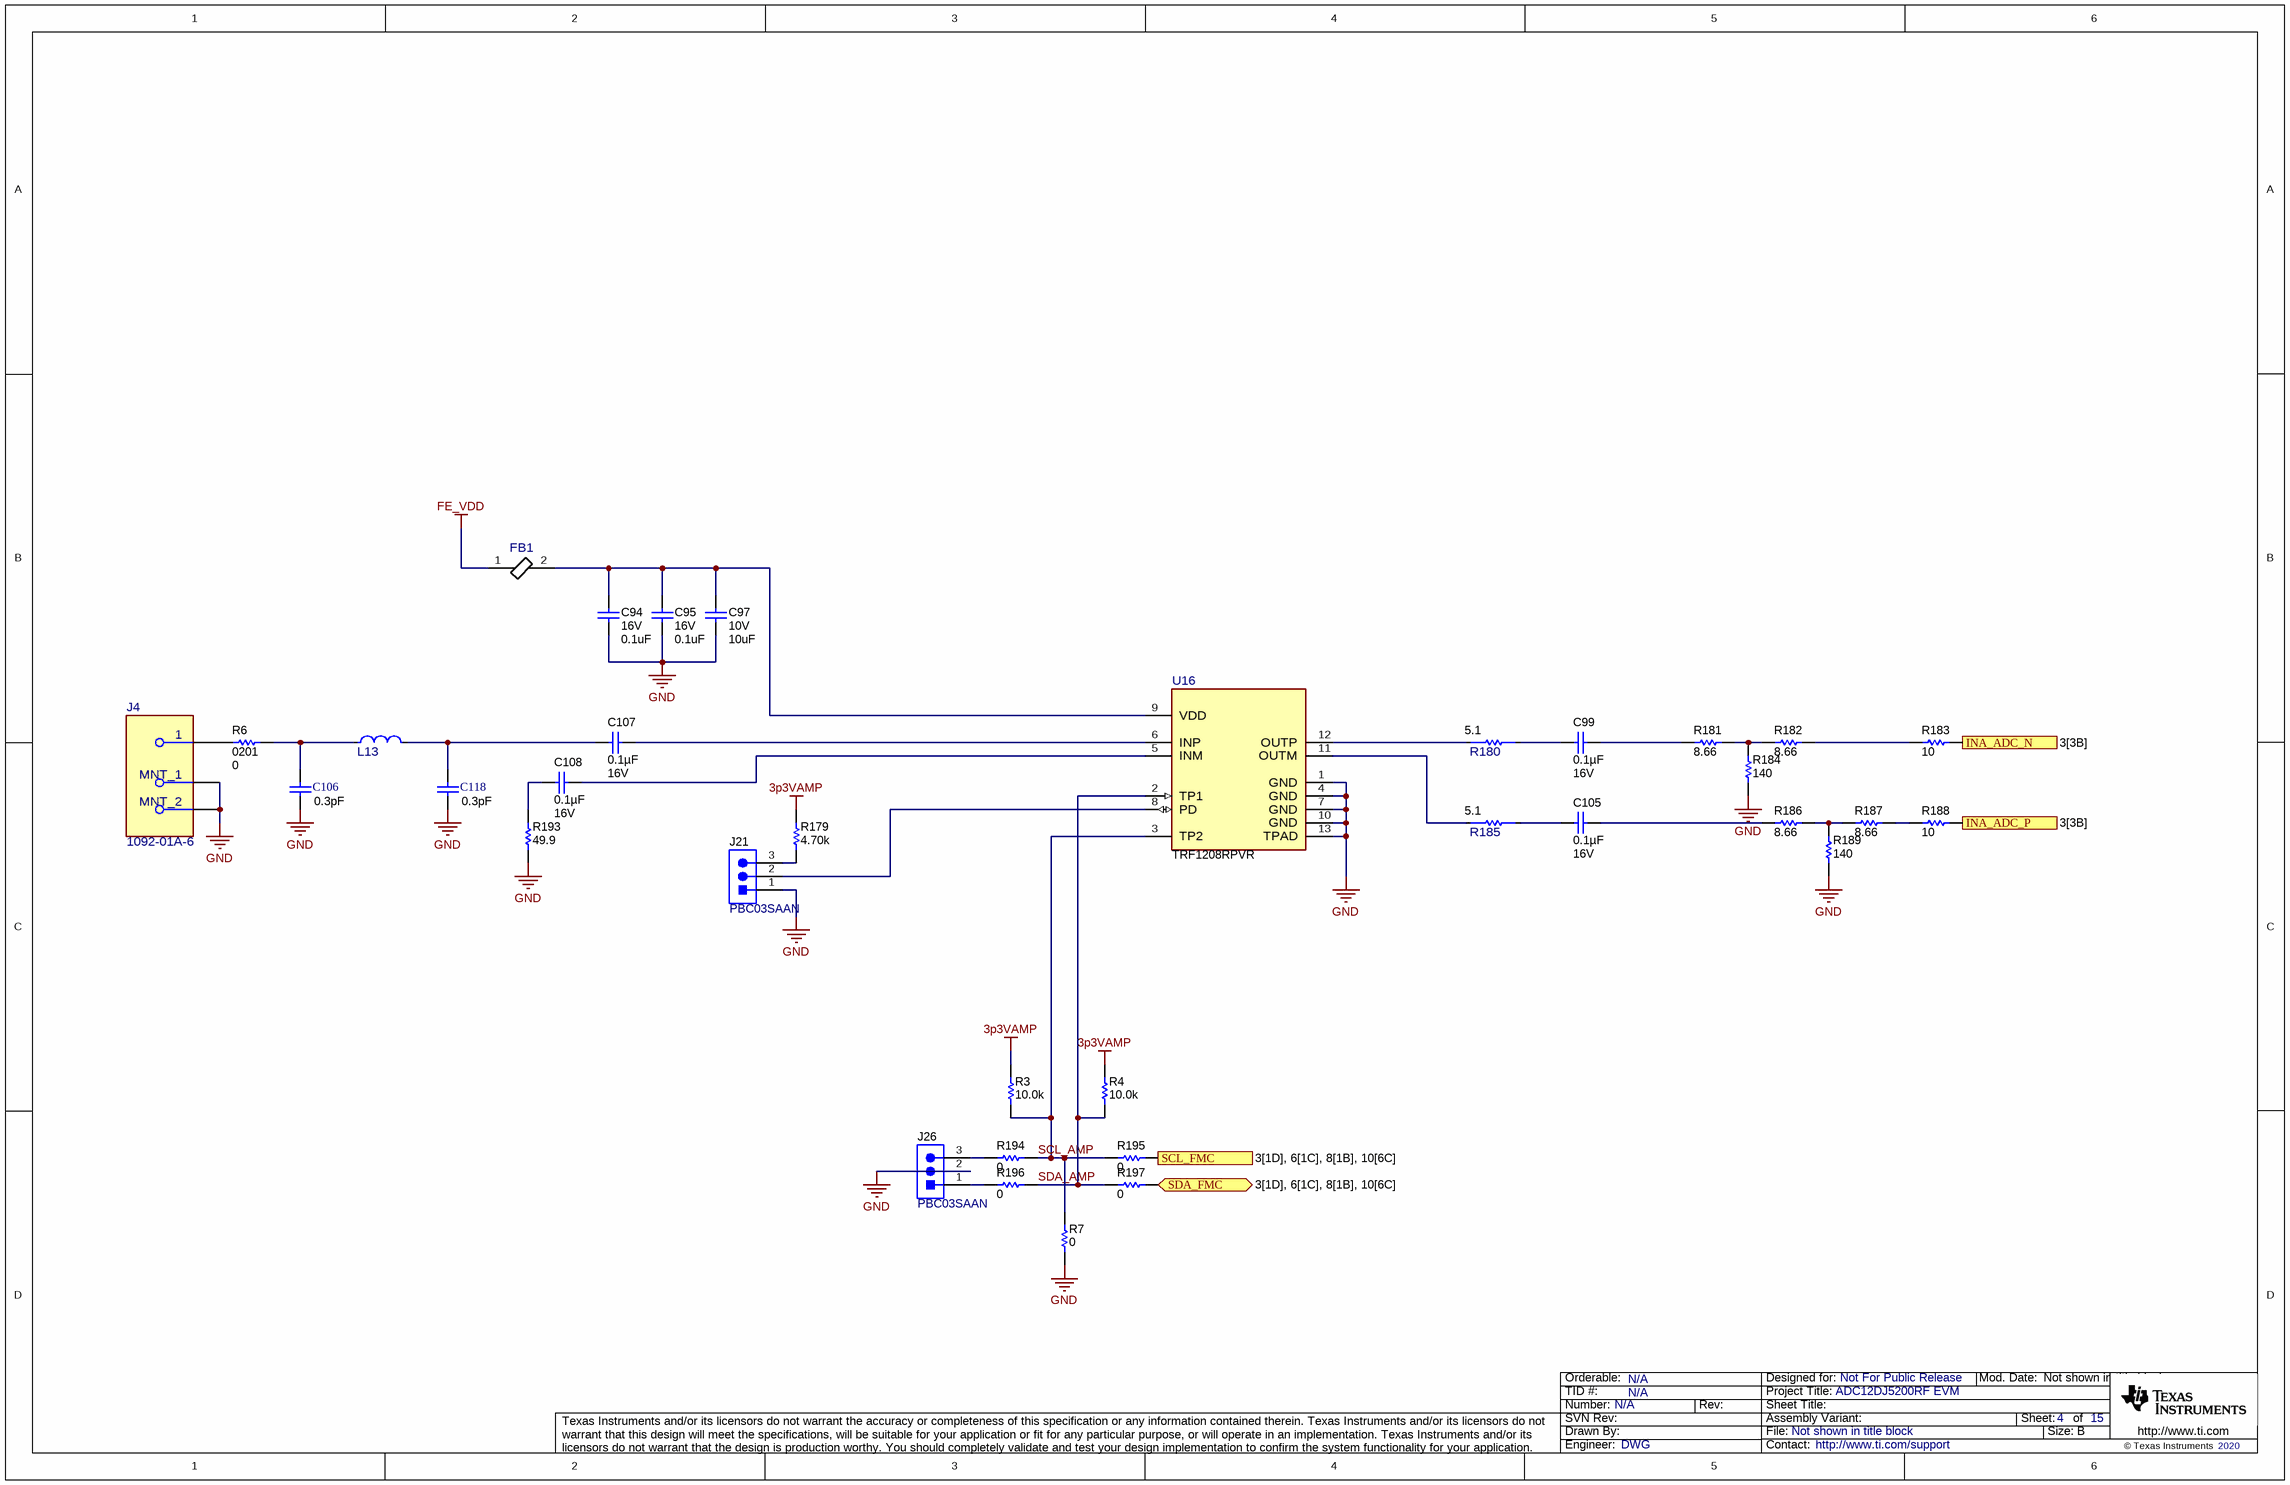
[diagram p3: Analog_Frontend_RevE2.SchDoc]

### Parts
C94  VDC_V: 16V  ValueDisplayed: 0.1uF  [0201]  (hidden comment: GRM033Z71C104KE14D)
C95  VDC_V: 16V  ValueDisplayed: 0.1uF  [0201]  (hidden comment: GRM033Z71C104KE14D)
C97  VDC_V: 10V  ValueDisplayed: 10uF  [0603]  (hidden comment: GRM188Z71A106MA73D)
C99  ValueDisplayed: 0.1µF  VDC_V: 16V  [0201_033]  (hidden comment: 0201BB104KW160)
C105  ValueDisplayed: 0.1µF  VDC_V: 16V  [0201_033]  (hidden comment: 0201BB104KW160)
C106  value 0.3pF  [CAPC0603X33X15LL03T05]  (hidden comment: GRM0335C1HR30BA01D)
C107  ValueDisplayed: 0.1µF  VDC_V: 16V  [0201_033]  (hidden comment: 0201BB104KW160)
C108  ValueDisplayed: 0.1µF  VDC_V: 16V  [0201_033]  (hidden comment: 0201BB104KW160)
C118  value 0.3pF  [CAPC0603X33X15LL03T05]  (hidden comment: GRM0335C1HR30BA01D)
FB1  BLM21SN300SN1D  [FP-BLM21SN300SN1D_0805-MFG]  (value not drawn)
J4  1092-01A-6  [FP-1092-01A-6_RF_JACK_18MM94_12MM7-MFG]
J21  PBC03SAAN  [PBC03SAAN]
J26  PBC03SAAN  [PBC03SAAN]
L13  LQW03AW1N8C00D  [FP-LQW03AW1N8C00D_0201-MFG]  (value not drawn)
R3  ValueDisplayed: 10.0k  [0201]  (hidden comment: CRCW020110K0FKED)
R4  ValueDisplayed: 10.0k  [0201]  (hidden comment: CRCW020110K0FKED)
R6  ValueDisplayed: 0  [0201]  (hidden comment: ERJ-1GN0R00C)
R7  ValueDisplayed: 0  [0201]  (hidden comment: ERJ-1GE0R00C)
R179  ValueDisplayed: 4.70k  [0603]  (hidden comment: RC0603FR-074K7L)
R180  Res_ohm: 5.1  [FP-ERJ-1GNJ5R1C_0201-MFG]  (hidden comment: ERJ-1GNJ5R1C)
R181  ValueDisplayed: 8.66  [0201]  (hidden comment: RC0201FR-078R66L)
R182  ValueDisplayed: 8.66  [0201]  (hidden comment: RC0201FR-078R66L)
R183  ValueDisplayed: 10  [0201]  (hidden comment: RC0201JR-0710RL)
R184  ValueDisplayed: 140  [0201]  (hidden comment: RC0201FR-07140RL)
R185  Res_ohm: 5.1  [FP-ERJ-1GNJ5R1C_0201-MFG]  (hidden comment: ERJ-1GNJ5R1C)
R186  ValueDisplayed: 8.66  [0201]  (hidden comment: RC0201FR-078R66L)
R187  ValueDisplayed: 8.66  [0201]  (hidden comment: RC0201FR-078R66L)
R188  ValueDisplayed: 10  [0201]  (hidden comment: RC0201JR-0710RL)
R189  ValueDisplayed: 140  [0201]  (hidden comment: RC0201FR-07140RL)
R193  ValueDisplayed: 49.9  [0201]  (hidden comment: ERJ-1GEF49R9C)
R194  ValueDisplayed: 0  [0201]  (hidden comment: ERJ-1GE0R00C)
R195  ValueDisplayed: 0  [0201]  (hidden comment: ERJ-1GE0R00C)
R196  ValueDisplayed: 0  [0201]  (hidden comment: ERJ-1GE0R00C)
R197  ValueDisplayed: 0  [0201]  (hidden comment: ERJ-1GE0R00C)
U16  TRF1208RPVR  [RPV0012A-MFG]

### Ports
INA_ADC_N (out, see 3[3B]), INA_ADC_P (out, see 3[3B]), SCL_FMC (out, see 3[1D], 6[1C], 8[1B], 10[6C]), SDA_FMC (bidir, see 3[1D], 6[1C], 8[1B], 10[6C])

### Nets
3p3VAMP: R3.2 R4.2 R179.2
FE_VDD: FB1.1
GND: C94.2 C95.2 C97.2 C106.1 C118.1 J4.2(MNT_1) J4.3(MNT_2) J21.1 J26.2 R7.1 R184.1 R189.1 R193.1 U16.1(GND) U16.4(GND) U16.7(GND) U16.10(GND) U16.13(TPAD)
INA_ADC_N: R183.2 ; port INA_ADC_N
INA_ADC_P: R188.2 ; port INA_ADC_P
SCL_AMP: R3.1 R7.2 R194.2 R195.1 U16.3(TP2)
SCL_FMC: R195.2 ; port SCL_FMC
SDA_AMP: R4.1 R196.2 R197.1 U16.2(TP1)
SDA_FMC: R197.2 ; port SDA_FMC
NetC94_1: C94.1 C95.1 C97.1 FB1.2 U16.9(VDD)
NetC99_1: C99.1 R181.1
NetC99_2: C99.2 R180.2
NetC105_1: C105.1 R186.1
NetC105_2: C105.2 R185.2
NetC106_2: C106.2 L13.1 R6.2
NetC107_1: C107.1 U16.6(INP)
NetC107_2: C107.2 C118.2 L13.2
NetC108_1: C108.1 U16.5(INM)
NetC108_2: C108.2 R193.2
NetJ4_1: J4.1 R6.1
NetJ21_2: J21.2 U16.8(PD)
NetJ21_3: J21.3 R179.1
NetJ26_1: J26.1 R196.1
NetJ26_3: J26.3 R194.1
NetR180_1: R180.1 U16.12(OUTP)
NetR181_2: R181.2 R182.1 R184.2
NetR182_2: R182.2 R183.1
NetR185_1: R185.1 U16.11(OUTM)
NetR186_2: R186.2 R187.1 R189.2
NetR187_2: R187.2 R188.1

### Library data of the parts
C94 C95 = CMP-0064970-1: CAP, CERM, 0.1 uF, 16 V,+/- 10%, X7R, 0201; Manufacturer: MuRata; TaMin_C: -55°C; Polarized: N; SizeAreaWB_mm2: 2.08; Value1: Unknown; U/M: EA; Value: 0.1uF; TaMax_C: 125°C; SizeZ_mm: 0.26; SizeX_mm: 0.6; SizeY_mm: 0.3; SizeArea_mm2: 0.18; Cap_F: 100nF; AEC Category: Q200
C97 = CMP-0007497-5: CAP, CERM, 10 uF, 10 V, +/- 20%, X7R, 0603; Manufacturer: MuRata; TaMin_C: -55°C; Polarized: N; SizeAreaWB_mm2: 4.68; Value1: Unknown; U/M: EA; Value: 10uF; TaMax_C: 125°C; SizeZ_mm: 1; SizeX_mm: 1.6; SizeY_mm: 0.8; SizeArea_mm2: 1.28; Cap_F: 10µF; AEC Category: Q200
C99 C105 C107 C108 = CMP-0860981-1: as C74 on sheet ADC_Input_RevE2
C106 C118 = CMP-2010-01234-1: Manufacturer: Murata; Voltage: 50V
FB1 = CMP-0081829-1: 30 Ohms @ 100MHz 1 Power Line Ferrite Bead 0805 (2012 Metric) 8.5A 4mOhm; Manufacturer: Murata; SizeZ_mm: 1.05mm; Impedance At Frequency: 30Ω @ 100MHz; Symbol Name: SYM-BLM21SN300SN1D; AEC Qualified: No; DCR_ohm: 0.004Ω
J4 = CMP-0088081-2: as J7 on sheet ADC_Input_RevE2
J21 J26 = CMP-0002334-1: Header, 100mil, 3x1, Gold, TH; Manufacturer: Sullins Connector Solutions; CNHeader: TRUE; Green_Lifecycle: Not Set; Green_REACh: Incomplete; CT: FALSE
L13 = CMP-0088640-1: Inductor RF Chip Unshielded Wirewound 1.8nH 0.2nH 250MHz 37Q-Factor Non Magnetic 520mA 100mOhm DCR 0201 T/R; Manufacturer: Murata; DCR_ohm: 0.1; SizeZ_mm: 0.45mm; Q Factor: 37; AEC Qualified: No; Self Resonant Frequency: 19GHz
R3 R4 = CMP-0027262-3: RES, 10.0 k, 1%, 0.05 W, 0201; Manufacturer: Vishay-Dale; Power_W: 50mW; TempCo: 100 ppm/C; Value_Code: 10k0; Value: 10.0k; EIA_Code: E96; Res_ohm: 10k; SizeX_mm: 0.6; SizeY_mm: 0.3; SizeZ_mm: 0.26; Value2: 0.05W; SizeArea_mm2: 0.18; AEC Qualified: N; VDC_V: 30V; AEC Category: Q200
R6 = CMP-0065361-1: RES, 0, 5%, .05 W, AEC-Q200 Grade 0, 0201; Manufacturer: Panasonic; Power_W: 50mW; Green_Lifecycle: Not Set; TempCo: ppm/C; Value_Code: 0000; Green_REACh: Incomplete; U/M: EA; Value: 0; EIA_Code: E24; SizeX_mm: 0.6; SizeY_mm: 0.3; SizeZ_mm: 0.26; Value2: .05W; SizeArea_mm2: 0.18; CompType: Resistor; AEC Qualified: Y; AEC Category: Q200
R7 R194-R197 = CMP-0027011-4: RES, 0, 5%, 0.05 W, AEC-Q200 Grade 1, 0201; Manufacturer: Panasonic; Power_W: 50mW; TempCo: 600 ppm/C; Value_Code: 0000; Value: 0; EIA_Code: E24; SizeX_mm: 0.6; SizeY_mm: 0.3; SizeZ_mm: 0.26; Value2: 0.05W; SizeArea_mm2: 0.18; AEC Qualified: Y; VDC_V: 15V; AEC Category: Q200; AEC Grade: 1; SizeAreaWB_mm2: 2.08
R179 = CMP-0023153-5: RES, 4.70 k, 1%, 0.1 W, 0603; Manufacturer: Yageo; Power_W: 100mW; TempCo: 100 ppm/C; Value_Code: 4k70; Value: 4.70k; Res_ohm: 4.7k; SizeX_mm: 1.6; SizeY_mm: 0.8; SizeZ_mm: 1; Value2: 0.1W; SizeArea_mm2: 1.28; AEC Qualified: N; VDC_V: 75V; AEC Category: Q200; SizeAreaWB_mm2: 4.68
R180 R185 = CMP-0088349-1: RES SMD 5.1 OHM 5% 1/20W 0201; Manufacturer: Panasonic; AEC Grade: Grade 1; Ciiva Ids: 1879726; TempCo: -100/600ppm/°C; VDC_V: 25V; AEC Qualified: Yes; Import Ts: 1521850358; Power_W: 50mW; SizeZ_mm: 0.26mm
R181 R182 R186 R187 = CMP-0750119-1: as R11 on sheet ADC_Input_RevE2
R183 R188 = CMP-0027021-3: RES, 10, 5%, 0.05 W, 0201; Manufacturer: Yageo America; Power_W: 50mW; TempCo: 350 ppm/C; Value_Code: 10R0; U/M: EA; Value: 10; EIA_Code: E24; SizeX_mm: 0.6; SizeY_mm: 0.3; SizeZ_mm: 0.26; Value2: 0.05W; SizeArea_mm2: 0.18; AEC Qualified: N; VDC_V: 25V; AEC Category: Q200
R184 R189 = CMP-0027355-2: as R12 on sheet ADC_Input_RevE2
R193 = CMP-0027289-3: as R1 on sheet ADC_RevE2
U16 = CMP-0090474-1: RF IC; Manufacturer: Texas Instruments; SizeZ_mm: 0.7mm; Standoff Height: 0mm

## Sheet Clocks_RevE2.SchDoc: EVM LMK
size 431 x 330 mm; Date: Not shown in title block; ApprovedBy: Not shown in title block; CheckedBy: Not shown in title block; Author: Not shown in title block; CompanyName: Not shown in title block; DrawnBy: DWG; Engineer: DWG; Organization: Not shown in title block; Address1: Not shown in title block; Address2: Not shown in title block; Address3: Not shown in title block; Address4: Not shown in title block; DocumentNumber: 5; Revision: Use project parameter SCH_Rev; SheetNumber: 5; SheetTotal: 15; PageSetup: Record=PageOptions¦CenterHorizontal=True¦CenterVertical=True¦PrintScale=1.00¦XCorrection=1.00¦YCorrection=1.00¦PrintKind=0¦BorderSize=5000000¦LeftOffset=0¦BottomOffset=0¦Orientation=2¦PaperLength=1000¦PaperWidth=1000¦Scale=100¦PaperSource=15¦PrintQuality=600¦MediaType=1¦DitherType=10¦PaperKind=Letter¦PrintScaleMode=1
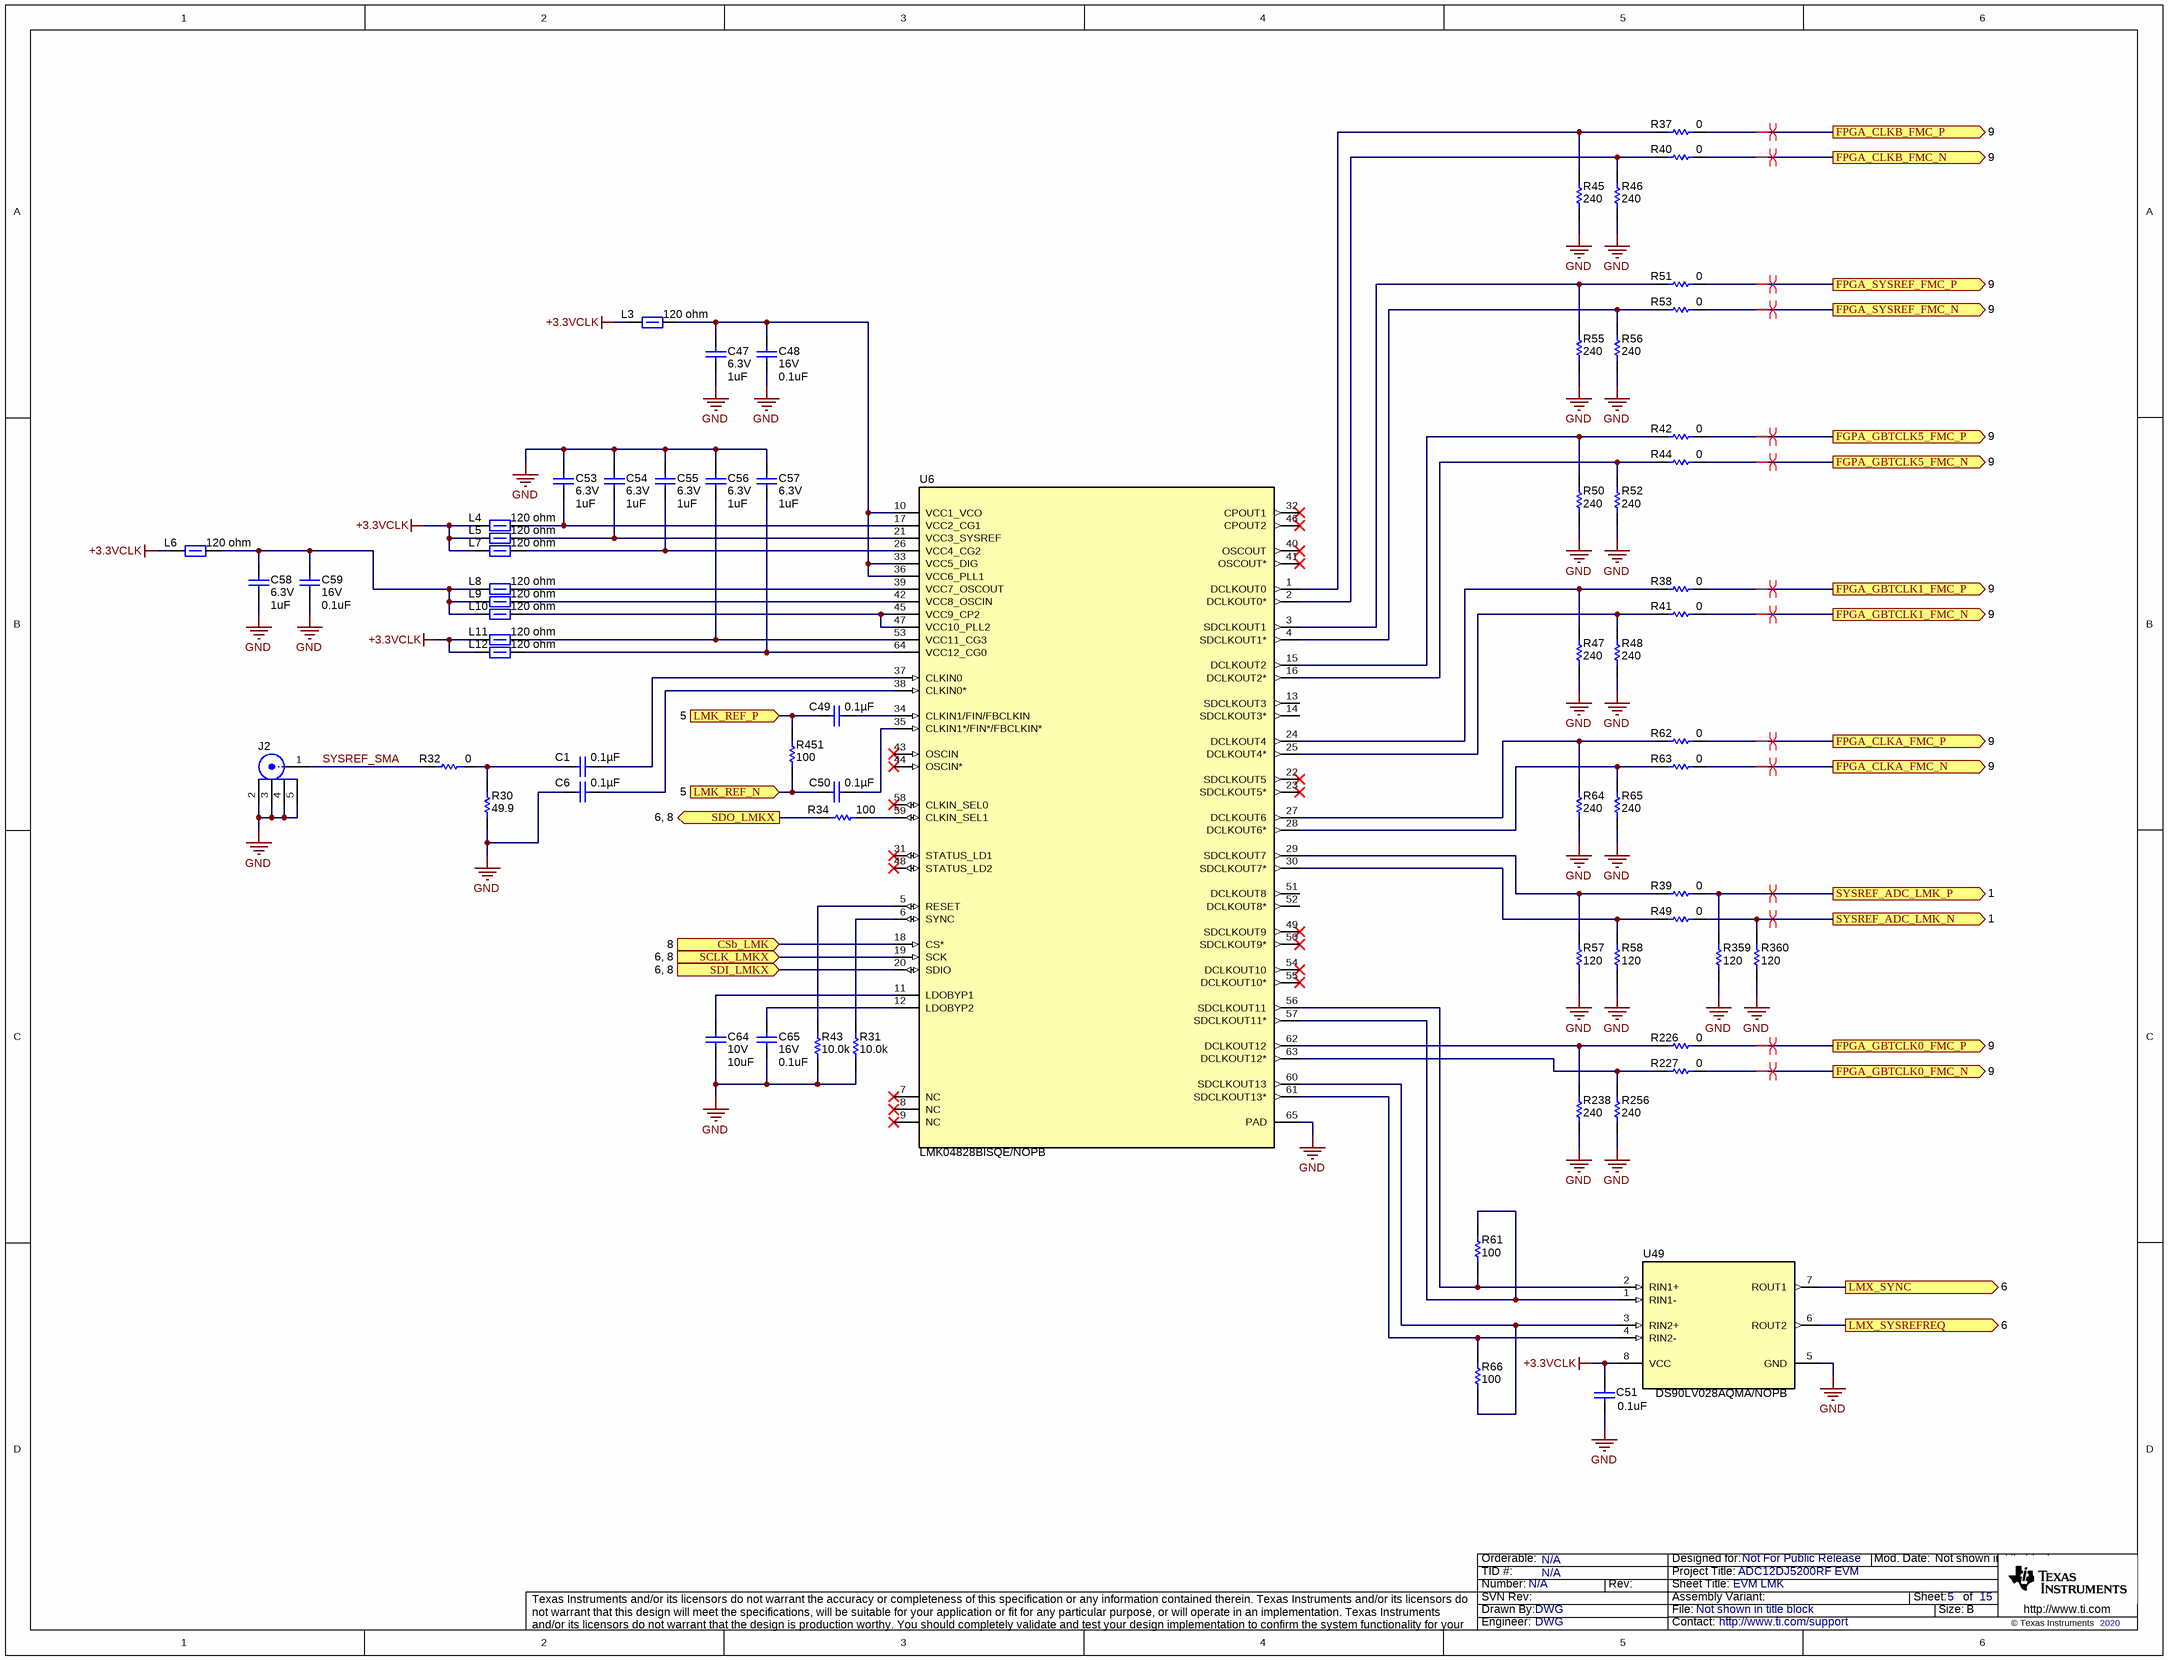
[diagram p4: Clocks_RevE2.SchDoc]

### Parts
C1  ValueDisplayed: 0.1µF  [0201_033L]  (hidden comment: 0201BB104KW160)
C6  ValueDisplayed: 0.1µF  [0201_033L]  (hidden comment: 0201BB104KW160)
C47  VDC_V: 6.3V  ValueDisplayed: 1uF  [0402L]  (hidden comment: GRM155R70J105KA12D)
C48  VDC_V: 16V  ValueDisplayed: 0.1uF  [0201L]  (hidden comment: GRM033Z71C104KE14D)
C49  ValueDisplayed: 0.1µF  [0201_033L]  (hidden comment: 0201BB104KW160)
C50  ValueDisplayed: 0.1µF  [0201_033L]  (hidden comment: 0201BB104KW160)
C51  ValueDisplayed: 0.1uF  [0201]  (hidden comment: GRM033Z71C104KE14D)
C53  VDC_V: 6.3V  ValueDisplayed: 1uF  [0402L]  (hidden comment: GRM155R70J105KA12D)
C54  VDC_V: 6.3V  ValueDisplayed: 1uF  [0402L]  (hidden comment: GRM155R70J105KA12D)
C55  VDC_V: 6.3V  ValueDisplayed: 1uF  [0402L]  (hidden comment: GRM155R70J105KA12D)
C56  VDC_V: 6.3V  ValueDisplayed: 1uF  [0402L]  (hidden comment: GRM155R70J105KA12D)
C57  VDC_V: 6.3V  ValueDisplayed: 1uF  [0402L]  (hidden comment: GRM155R70J105KA12D)
C58  VDC_V: 6.3V  ValueDisplayed: 1uF  [0402L]  (hidden comment: GRM155R70J105KA12D)
C59  VDC_V: 16V  ValueDisplayed: 0.1uF  [0201L]  (hidden comment: GRM033Z71C104KE14D)
C64  VDC_V: 10V  ValueDisplayed: 10uF  [0603L]  (hidden comment: GRM188Z71A106MA73D)
C65  VDC_V: 16V  ValueDisplayed: 0.1uF  [0201L]  (hidden comment: GRM033Z71C104KE14D)
J2  SASF546-P26-X1  [CONN_LTI_SASF546-P26-X1]  (value not drawn)
L3  ValueDisplayed: 120 ohm  [0402L]  (hidden comment: 74279271)
L4  ValueDisplayed: 120 ohm  [0402L]  (hidden comment: 74279271)
L5  ValueDisplayed: 120 ohm  [0402L]  (hidden comment: 74279271)
L6  ValueDisplayed: 120 ohm  [0402L]  (hidden comment: 74279271)
L7  ValueDisplayed: 120 ohm  [0402L]  (hidden comment: 74279271)
L8  ValueDisplayed: 120 ohm  [0402L]  (hidden comment: 74279271)
L9  ValueDisplayed: 120 ohm  [0402L]  (hidden comment: 74279271)
L10  ValueDisplayed: 120 ohm  [0402L]  (hidden comment: 74279271)
L11  ValueDisplayed: 120 ohm  [0402L]  (hidden comment: 74279271)
L12  ValueDisplayed: 120 ohm  [0402L]  (hidden comment: 74279271)
R30  ValueDisplayed: 49.9  [0402L]  (hidden comment: ERJ-2RKF49R9X)
R31  ValueDisplayed: 10.0k  [0201L]  (hidden comment: RC0201FR-7D10KL)
R32  ValueDisplayed: 0  [0201L]  (hidden comment: CRCW02010000Z0ED)
R34  ValueDisplayed: 100  [0201L]  (hidden comment: RC0201FS-7D100RL)
R37  ValueDisplayed: 0  [0201L]  (hidden comment: CRCW02010000Z0ED)
R38  ValueDisplayed: 0  [0201L]  (hidden comment: CRCW02010000Z0ED)
R39  ValueDisplayed: 0  [0201L]  (hidden comment: CRCW02010000Z0ED)
R40  ValueDisplayed: 0  [0201L]  (hidden comment: CRCW02010000Z0ED)
R41  ValueDisplayed: 0  [0201L]  (hidden comment: CRCW02010000Z0ED)
R42  ValueDisplayed: 0  [0201L]  (hidden comment: CRCW02010000Z0ED)
R43  ValueDisplayed: 10.0k  [0201L]  (hidden comment: RC0201FR-7D10KL)
R44  ValueDisplayed: 0  [0201L]  (hidden comment: CRCW02010000Z0ED)
R45  ValueDisplayed: 240  [0201L]  (hidden comment: RC0201FR-7D240RL)
R46  ValueDisplayed: 240  [0201L]  (hidden comment: RC0201FR-7D240RL)
R47  ValueDisplayed: 240  [0201L]  (hidden comment: RC0201FR-7D240RL)
R48  ValueDisplayed: 240  [0201L]  (hidden comment: RC0201FR-7D240RL)
R49  ValueDisplayed: 0  [0201L]  (hidden comment: CRCW02010000Z0ED)
R50  ValueDisplayed: 240  [0201L]  (hidden comment: RC0201FR-7D240RL)
R51  ValueDisplayed: 0  [0201L]  (hidden comment: CRCW02010000Z0ED)
R52  ValueDisplayed: 240  [0201L]  (hidden comment: RC0201FR-7D240RL)
R53  ValueDisplayed: 0  [0201L]  (hidden comment: CRCW02010000Z0ED)
R55  ValueDisplayed: 240  [0201L]  (hidden comment: RC0201FR-7D240RL)
R56  ValueDisplayed: 240  [0201L]  (hidden comment: RC0201FR-7D240RL)
R57  ValueDisplayed: 120  [0201L]  (hidden comment: RC0201FR-07120RL)
R58  ValueDisplayed: 120  [0201L]  (hidden comment: RC0201FR-07120RL)
R61  ValueDisplayed: 100  [0201L]  (hidden comment: RC0201FS-7D100RL)
R62  ValueDisplayed: 0  [0201L]  (hidden comment: CRCW02010000Z0ED)
R63  ValueDisplayed: 0  [0201L]  (hidden comment: CRCW02010000Z0ED)
R64  ValueDisplayed: 240  [0201L]  (hidden comment: RC0201FR-7D240RL)
R65  ValueDisplayed: 240  [0201L]  (hidden comment: RC0201FR-7D240RL)
R66  ValueDisplayed: 100  [0201L]  (hidden comment: RC0201FS-7D100RL)
R226  ValueDisplayed: 0  [0201L]  (hidden comment: CRCW02010000Z0ED)
R227  ValueDisplayed: 0  [0201L]  (hidden comment: CRCW02010000Z0ED)
R238  ValueDisplayed: 240  [0201L]  (hidden comment: RC0201FR-7D240RL)
R256  ValueDisplayed: 240  [0201L]  (hidden comment: RC0201FR-7D240RL)
R359  ValueDisplayed: 120  [0201L]  (hidden comment: RC0201FR-07120RL)
R360  ValueDisplayed: 120  [0201L]  (hidden comment: RC0201FR-07120RL)
R451  ValueDisplayed: 100  [0201L]  (hidden comment: RC0201FS-7D100RL)
U6  LMK04828BISQE/NOPB  [NKD0064A]
U49  DS90LV028AQMA/NOPB  [D0008A_N]

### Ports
CSb_LMK (in, see 8), FGPA_GBTCLK5_FMC_N (out, see 9), FGPA_GBTCLK5_FMC_P (out, see 9), FPGA_CLKA_FMC_N (out, see 9), FPGA_CLKA_FMC_P (out, see 9), FPGA_CLKB_FMC_N (out, see 9), FPGA_CLKB_FMC_P (out, see 9), FPGA_GBTCLK0_FMC_N (out, see 9), FPGA_GBTCLK0_FMC_P (out, see 9), FPGA_GBTCLK1_FMC_N (out, see 9), FPGA_GBTCLK1_FMC_P (out, see 9), FPGA_SYSREF_FMC_N (out, see 9), FPGA_SYSREF_FMC_P (out, see 9), LMK_REF_N (in, see 5), LMK_REF_P (in, see 5), LMX_SYNC (out, see 6), LMX_SYSREFREQ (out, see 6), SCLK_LMKX (in, see 6, 8), SDI_LMKX (in, see 6, 8), SDO_LMKX (out, see 6, 8), SYSREF_ADC_LMK_N (out, see 1), SYSREF_ADC_LMK_P (out, see 1)

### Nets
+3.3VCLK: C51.1 L3.1 L4.1 L5.1 L6.1 L7.1 L11.1 L12.1 U49.8(VCC)
GND: C6.2 C47.2 C48.2 C51.2 C53.1 C54.1 C55.1 C56.1 C57.1 C58.2 C59.2 C64.2 C65.2 J2.2 J2.3 J2.4 J2.5 R30.1 R31.2 R43.2 R45.1 R46.1 R47.1 R48.1 R50.1 R52.1 R55.1 R56.1 R57.1 R58.1 R64.1 R65.1 R238.1 R256.1 R359.1 R360.1 U6.65(PAD) U49.5(GND)
CSb_LMK: U6.18(CS*) ; port CSb_LMK
FGPA_GBTCLK5_FMC_N: R44.2 ; port FGPA_GBTCLK5_FMC_N
FGPA_GBTCLK5_FMC_P: R42.2 ; port FGPA_GBTCLK5_FMC_P
FPGA_CLKA_FMC_N: R63.2 ; port FPGA_CLKA_FMC_N
FPGA_CLKA_FMC_P: R62.2 ; port FPGA_CLKA_FMC_P
FPGA_CLKB_FMC_N: R40.2 ; port FPGA_CLKB_FMC_N
FPGA_CLKB_FMC_P: R37.2 ; port FPGA_CLKB_FMC_P
FPGA_GBTCLK0_FMC_N: R227.2 ; port FPGA_GBTCLK0_FMC_N
FPGA_GBTCLK0_FMC_P: R226.2 ; port FPGA_GBTCLK0_FMC_P
FPGA_GBTCLK1_FMC_N: R41.2 ; port FPGA_GBTCLK1_FMC_N
FPGA_GBTCLK1_FMC_P: R38.2 ; port FPGA_GBTCLK1_FMC_P
FPGA_SYSREF_FMC_N: R53.2 ; port FPGA_SYSREF_FMC_N
FPGA_SYSREF_FMC_P: R51.2 ; port FPGA_SYSREF_FMC_P
LMK_REF_N: C50.2 R451.1 ; port LMK_REF_N
LMK_REF_P: C49.2 R451.2 ; port LMK_REF_P
LMX_SYNC: U49.7(ROUT1) ; port LMX_SYNC
LMX_SYSREFREQ: U49.6(ROUT2) ; port LMX_SYSREFREQ
SCLK_LMKX: U6.19(SCK) ; port SCLK_LMKX
SDI_LMKX: U6.20(SDIO) ; port SDI_LMKX
SDO_LMKX: R34.2 ; port SDO_LMKX
SYSREF_ADC_LMK_N: R49.2 R360.2 ; port SYSREF_ADC_LMK_N
SYSREF_ADC_LMK_P: R39.2 R359.2 ; port SYSREF_ADC_LMK_P
SYSREF_SMA: J2.1 R32.1
NetC1_1: C1.1 U6.37(CLKIN0)
NetC1_2: C1.2 R30.2 R32.2
NetC6_1: C6.1 U6.38(CLKIN0*)
NetC47_1: C47.1 C48.1 L3.2 U6.10(VCC1_VCO) U6.33(VCC5_DIG) U6.36(VCC6_PLL1)
NetC49_1: C49.1 U6.34(CLKIN1/FIN/FBCLKIN)
NetC50_1: C50.1 U6.35(CLKIN1*/FIN*/FBCLKIN*)
NetC53_2: C53.2 L4.2 U6.17(VCC2_CG1)
NetC54_2: C54.2 L5.2 U6.21(VCC3_SYSREF)
NetC55_2: C55.2 L7.2 U6.26(VCC4_CG2)
NetC56_2: C56.2 L11.2 U6.53(VCC11_CG3)
NetC57_2: C57.2 L12.2 U6.64(VCC12_CG0)
NetC58_1: C58.1 C59.1 L6.2 L8.1 L9.1 L10.1
NetC64_1: C64.1 U6.11(LDOBYP1)
NetC65_1: C65.1 U6.12(LDOBYP2)
NetL8_2: L8.2 U6.39(VCC7_OSCOUT)
NetL9_2: L9.2 U6.42(VCC8_OSCIN)
NetL10_2: L10.2 U6.45(VCC9_CP2) U6.47(VCC10_PLL2)
NetR31_1: R31.1 U6.6(SYNC)
NetR34_1: R34.1 U6.59(CLKIN_SEL1)
NetR37_1: R37.1 R45.2 U6.1(DCLKOUT0)
NetR38_1: R38.1 R47.2 U6.24(DCLKOUT4)
NetR39_1: R39.1 R57.2 U6.29(SDCLKOUT7)
NetR40_1: R40.1 R46.2 U6.2(DCLKOUT0*)
NetR41_1: R41.1 R48.2 U6.25(DCLKOUT4*)
NetR42_1: R42.1 R50.2 U6.15(DCLKOUT2)
NetR43_1: R43.1 U6.5(RESET)
NetR44_1: R44.1 R52.2 U6.16(DCLKOUT2*)
NetR49_1: R49.1 R58.2 U6.30(SDCLKOUT7*)
NetR51_1: R51.1 R55.2 U6.3(SDCLKOUT1)
NetR53_1: R53.1 R56.2 U6.4(SDCLKOUT1*)
NetR61_1: R61.1 U6.57(SDCLKOUT11*) U49.1(RIN1-)
NetR61_2: R61.2 U6.56(SDCLKOUT11) U49.2(RIN1+)
NetR62_1: R62.1 R64.2 U6.27(DCLKOUT6)
NetR63_1: R63.1 R65.2 U6.28(DCLKOUT6*)
NetR66_1: R66.1 U6.61(SDCLKOUT13*) U49.4(RIN2-)
NetR66_2: R66.2 U6.60(SDCLKOUT13) U49.3(RIN2+)
NetR226_1: R226.1 R238.2 U6.62(DCLKOUT12)
NetR227_1: R227.1 R256.2 U6.63(DCLKOUT12*)

Not connected (* = marked no-connect by the designer): U6 7(NC)* 8(NC)* 9(NC)* 13(SDCLKOUT3) 14(SDCLKOUT3*) 22(SDCLKOUT5)* 23(SDCLKOUT5*)* 31(STATUS_LD1)* 32(CPOUT1)* 40(OSCOUT)* 41(OSCOUT*)* 43(OSCIN)* 44(OSCIN*)* 46(CPOUT2)* 48(STATUS_LD2)* 49(SDCLKOUT9)* 50(SDCLKOUT9*)* 51(DCLKOUT8) 52(DCLKOUT8*) 54(DCLKOUT10)* 55(DCLKOUT10*)* 58(CLKIN_SEL0)*

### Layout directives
differential pair: FGPA_GBTCLK5_FMC_N, FGPA_GBTCLK5_FMC_P, FPGA_CLKA_FMC_N, FPGA_CLKA_FMC_P, FPGA_CLKB_FMC_N, FPGA_CLKB_FMC_P, FPGA_GBTCLK0_FMC_N, FPGA_GBTCLK0_FMC_P, FPGA_GBTCLK1_FMC_N, FPGA_GBTCLK1_FMC_P, FPGA_SYSREF_FMC_N, FPGA_SYSREF_FMC_P, SYSREF_ADC_LMK_N, SYSREF_ADC_LMK_P

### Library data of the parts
C1 C6 C49 C50 = CMP-0860981-1: as C2 on sheet ADC_RevE2
C47 C53-C58 = CMP-0064947-2: CAP, CERM, 1 uF, 6.3 V,+/- 10%, X7R, 0402; Manufacturer: MuRata; TaMin_C: -55°C; Polarized: N; SizeAreaWB_mm2: 3; Value1: Unknown; U/M: EA; Value: 1uF; TaMax_C: 125°C; SizeZ_mm: 0.6; SizeX_mm: 1; SizeY_mm: 0.5; Cap_Case: 0402; Cap_F: 1µF; AEC Category: Q200
C48 C59 C65 = CMP-0064970-1: as C157 on sheet ADC_Power_RevE2
C51 = CMP-0064970-1: CAP, CERM, 0.1 uF, 16 V,+/- 10%, X7R, 0201; Manufacturer: MuRata; TaMin_C: -55°C; Polarized: N; SizeAreaWB_mm2: 2.08; Value1: Unknown; U/M: EA; Value: 0.1uF; TaMax_C: 125°C; SizeZ_mm: 0.26; SizeX_mm: 0.6; SizeY_mm: 0.3; Value2: 16V; SizeArea_mm2: 0.18; CompType: Capacitor; Cap_F: 100nF; AEC Category: Q200
C64 = CMP-0007497-5: CAP, CERM, 10 uF, 10 V, +/- 20%, X7R, 0603; Manufacturer: MuRata; TaMin_C: -55°C; Polarized: N; SizeAreaWB_mm2: 4.68; Value1: Unknown; U/M: EA; Value: 10uF; TaMax_C: 125°C; SizeZ_mm: 1; SizeX_mm: 1.6; SizeY_mm: 0.8; Cap_Case: 0603; SizeArea_mm2: 1.28; CompType: Capacitor; Cap_F: 10µF; AEC Category: Q200
J2 = CMP-0055826-1: as J6 on sheet ADC_Input_RevE2
L3-L12 = CMP-0003214-1: Ferrite Bead, 120 ohm @ 100 MHz, 0.5 A, 0402; Manufacturer: Wurth Elektronik; Ztyp@1GHz_Ohm: 175.42; ZTyp@100MHz_Ohm: 120; SizeAreaWB_mm2: 3; DCR_ohm: 2d; Value1: 0.2 ohm; Value: 120 ohm; Imax_A: 5dA; SizeZ_mm: 0.6; SizeX_mm: 1; SizeY_mm: 0.5; Value2: 0.5A
R30 = CMP-0026703-1: RES, 49.9, 1%, 0.1 W, AEC-Q200 Grade 0, 0402; Manufacturer: Panasonic; Power_W: 100mW; TempCo: 100 ppm/C; Value_Code: 49R9; U/M: EA; Value: 49.9; EIA_Code: E96; SizeX_mm: 1; SizeY_mm: 0.5; SizeZ_mm: 0.6; Value2: 0.1W; AEC Qualified: Y; VDC_V: 50V; AEC Grade: 0; AEC Category: Q200
R31 = CMP-0027945-1: RES, 10.0 k, 1%, 0.05 W, 0201; Manufacturer: Yageo America; Power_W: 50mW; TempCo: 200 ppm/C; Value_Code: 10k0; U/M: EA; Value: 10.0k; EIA_Code: E96; Res_ohm: 10k; SizeX_mm: 0.6; SizeY_mm: 0.3; SizeZ_mm: 0.26; Value2: 0.05W; SizeArea_mm2: 0.18; CompType: Resistor; AEC Qualified: N; VDC_V: 25V; AEC Category: Q200
R32 R37 R38 R40-R42 R44 R51 R53 R62 R63 R226 R227 = CMP-0027008-4: as R20 on sheet ADC_RevE2
R34 = CMP-0028070-1: RES, 100, 1%, 0.05 W, 0201; Manufacturer: Yageo America; Power_W: 50mW; TempCo: 200 ppm/C; Value_Code: 100R; U/M: EA; Value: 100; EIA_Code: E96; SizeX_mm: 0.6; SizeY_mm: 0.3; SizeZ_mm: 0.26; Value2: 0.05W; SizeArea_mm2: 0.18; AEC Qualified: N; VDC_V: 25V; AEC Category: Q200
R39 R49 = CMP-0027008-4: as R171 on sheet ADC_RevE2
R43 = CMP-0027945-1: as R24 on sheet ADC_RevE2
R45 = CMP-0027984-1: RES, 240, 1%, 0.05 W, 0201; Manufacturer: Yageo America; Power_W: 50mW; TempCo: 200 ppm/C; Value_Code: 240R; U/M: EA; Value: 240; SizeX_mm: 0.6; SizeY_mm: 0.3; SizeZ_mm: 0.26; Value2: 0.05W; SizeArea_mm2: 0.18; CompType: Resistor; AEC Qualified: N; VDC_V: 25V; AEC Category: Q200
R46-R48 R50 R52 R55 R56 R64 R65 R238 R256 = CMP-0027984-1: RES, 240, 1%, 0.05 W, 0201; Manufacturer: Yageo America; Power_W: 50mW; TempCo: 200 ppm/C; Value_Code: 240R; U/M: EA; Value: 240; SizeX_mm: 0.6; SizeY_mm: 0.3; SizeZ_mm: 0.26; Value2: 0.05W; SizeArea_mm2: 0.18; AEC Qualified: N; VDC_V: 25V; AEC Category: Q200
R57 R58 = CMP-0027327-2: RES, 120, 1%, 0.05 W, 0201; Manufacturer: Yageo America; Power_W: 50mW; TempCo: 200 ppm/C; Value_Code: 120R; U/M: EA; Value: 120; SizeX_mm: 0.6; SizeY_mm: 0.3; SizeZ_mm: 0.26; Value2: 0.05W; SizeArea_mm2: 0.18; AEC Qualified: N; VDC_V: 25V; AEC Category: Q200
R61 R66 R451 = CMP-0028070-1: RES, 100, 1%, 0.05 W, 0201; Manufacturer: Yageo America; Power_W: 50mW; TempCo: 200 ppm/C; Value_Code: 100R; U/M: EA; Value: 100; EIA_Code: E96; SizeX_mm: 0.6; SizeY_mm: 0.3; SizeZ_mm: 0.26; Value2: 0.05W; SizeArea_mm2: 0.18; CompType: Resistor; AEC Qualified: N; VDC_V: 25V; AEC Category: Q200
R359 R360 = CMP-0027327-2: RES, 120, 1%, 0.05 W, 0201; Manufacturer: Yageo America; Power_W: 50mW; TempCo: 200 ppm/C; Value_Code: 120R; U/M: EA; Value: 120; SizeX_mm: 0.6; SizeY_mm: 0.3; SizeZ_mm: 0.26; Value2: 0.05W; SizeArea_mm2: 0.18; CompType: Resistor; AEC Qualified: N; VDC_V: 25V; AEC Category: Q200
U6 = CMP-0084462-1: Ultra Low Jitter Synthesizer and Jitter Cleaner, NKD0064A (WQFN-64); Manufacturer: Texas Instruments; Alternate PartNumber: LMK04828BISQX/NOPB; AEC Category: Q200; Rating: Catalog; SizeZ_mm: 0.8; AEC Qualified: N; CompType: IC; SizeArea_mm2: 81; SizeX_mm: 9; SizeAreaWB_mm2: 121
U49 = CMP-0069724-2: Automotive LVDS Dual Differential Line Receiver, D0008A (SOIC-8); Manufacturer: Texas Instruments; CompType: IC; AEC Category: Q200; AEC Qualified: Y; SizeArea_mm2: 30.38; SizeAreaWB_mm2: 56.58; SizeX_mm: 4.9; SizeY_mm: 6.2; SizeZ_mm: 1.75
